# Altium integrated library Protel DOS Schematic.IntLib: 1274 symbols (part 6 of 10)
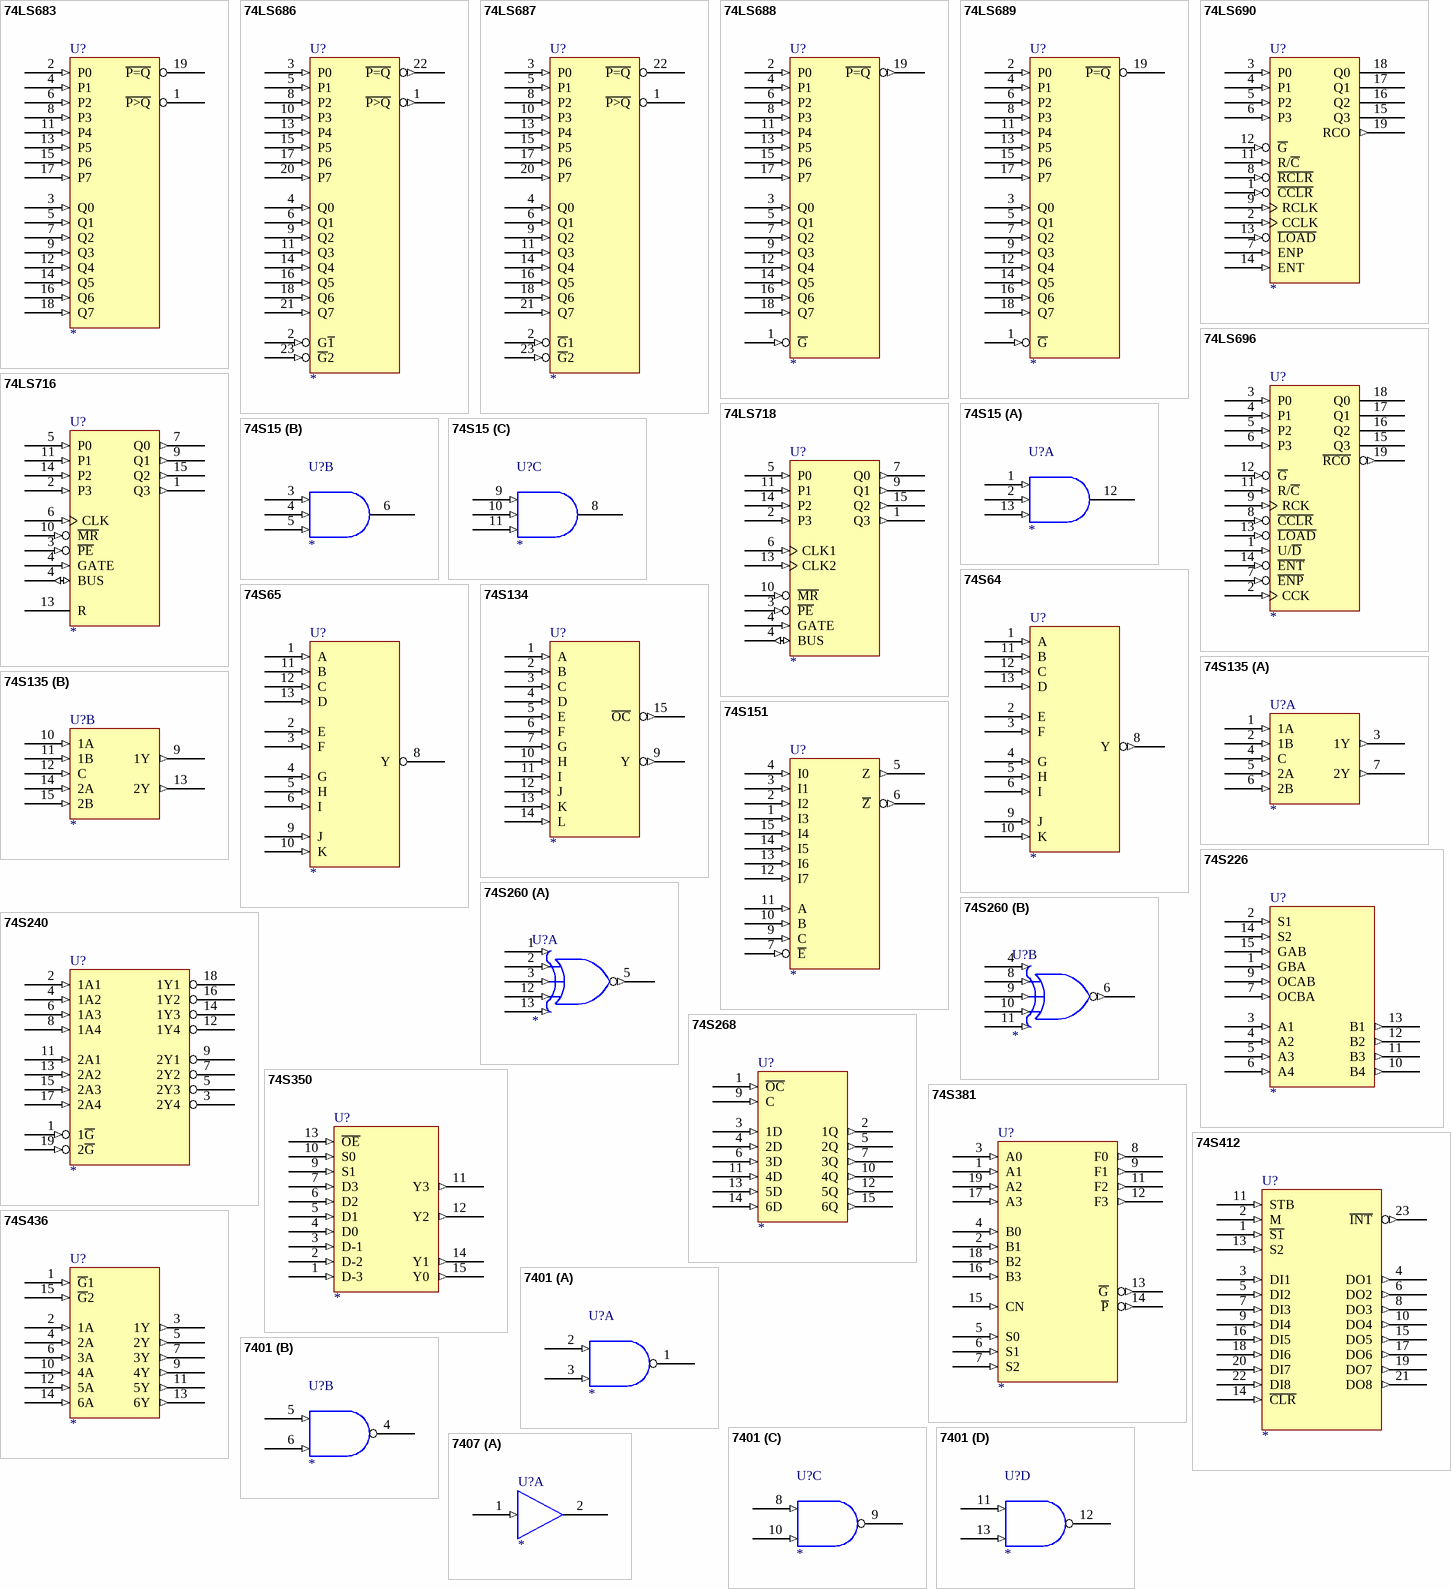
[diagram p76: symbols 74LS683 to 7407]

## 74S412
designator U?
footprint DIP-24
pins: 1 ~{S1} (in), 2 M (in), 3 DI1 (in), 4 DO1 (out), 5 DI2 (in), 6 DO2 (out), 7 DI3 (in), 8 DO3 (out), 9 DI4 (in), 10 DO4 (out), 11 STB (in), 12 GND (power) hidden to GND, 13 S2 (in), 14 ~{CLR} (in), 15 DO5 (out), 16 DI5 (in), 17 DO6 (out), 18 DI6 (in), 19 DO7 (out), 20 DI7 (in), 21 DO8 (out), 22 DI8 (in), 23 ~{INT} (out), 24 VCC (power) hidden to VCC
2 alternate drawings of the same symbol

## 74S436
designator U?
footprint DIP-16
pins: 1 ~{G}1 (in), 2 1A (in), 3 1Y (out), 4 2A (in), 5 2Y (out), 6 3A (in), 7 3Y (out), 8 GND (power) hidden to GND, 9 4Y (out), 10 4A (in), 11 5Y (out), 12 5A (in), 13 6Y (out), 14 6A (in), 15 ~{G}2 (in), 16 VCC (power) hidden to VCC
2 alternate drawings of the same symbol

## 7401
designator U?
footprint DIP-14
part A pins: 1 (oc), 2 (in), 3 (in), 7 GND (power) hidden to GND, 14 VCC (power) hidden to VCC
part B pins: 4 (oc), 5 (in), 6 (in), 7 GND (power) hidden to GND, 14 VCC (power) hidden to VCC
part C pins: 7 GND (power) hidden to GND, 8 (in), 9 (oc), 10 (in), 14 VCC (power) hidden to VCC
part D pins: 7 GND (power) hidden to GND, 11 (in), 12 (oc), 13 (in), 14 VCC (power) hidden to VCC
2 alternate drawings of the same symbol

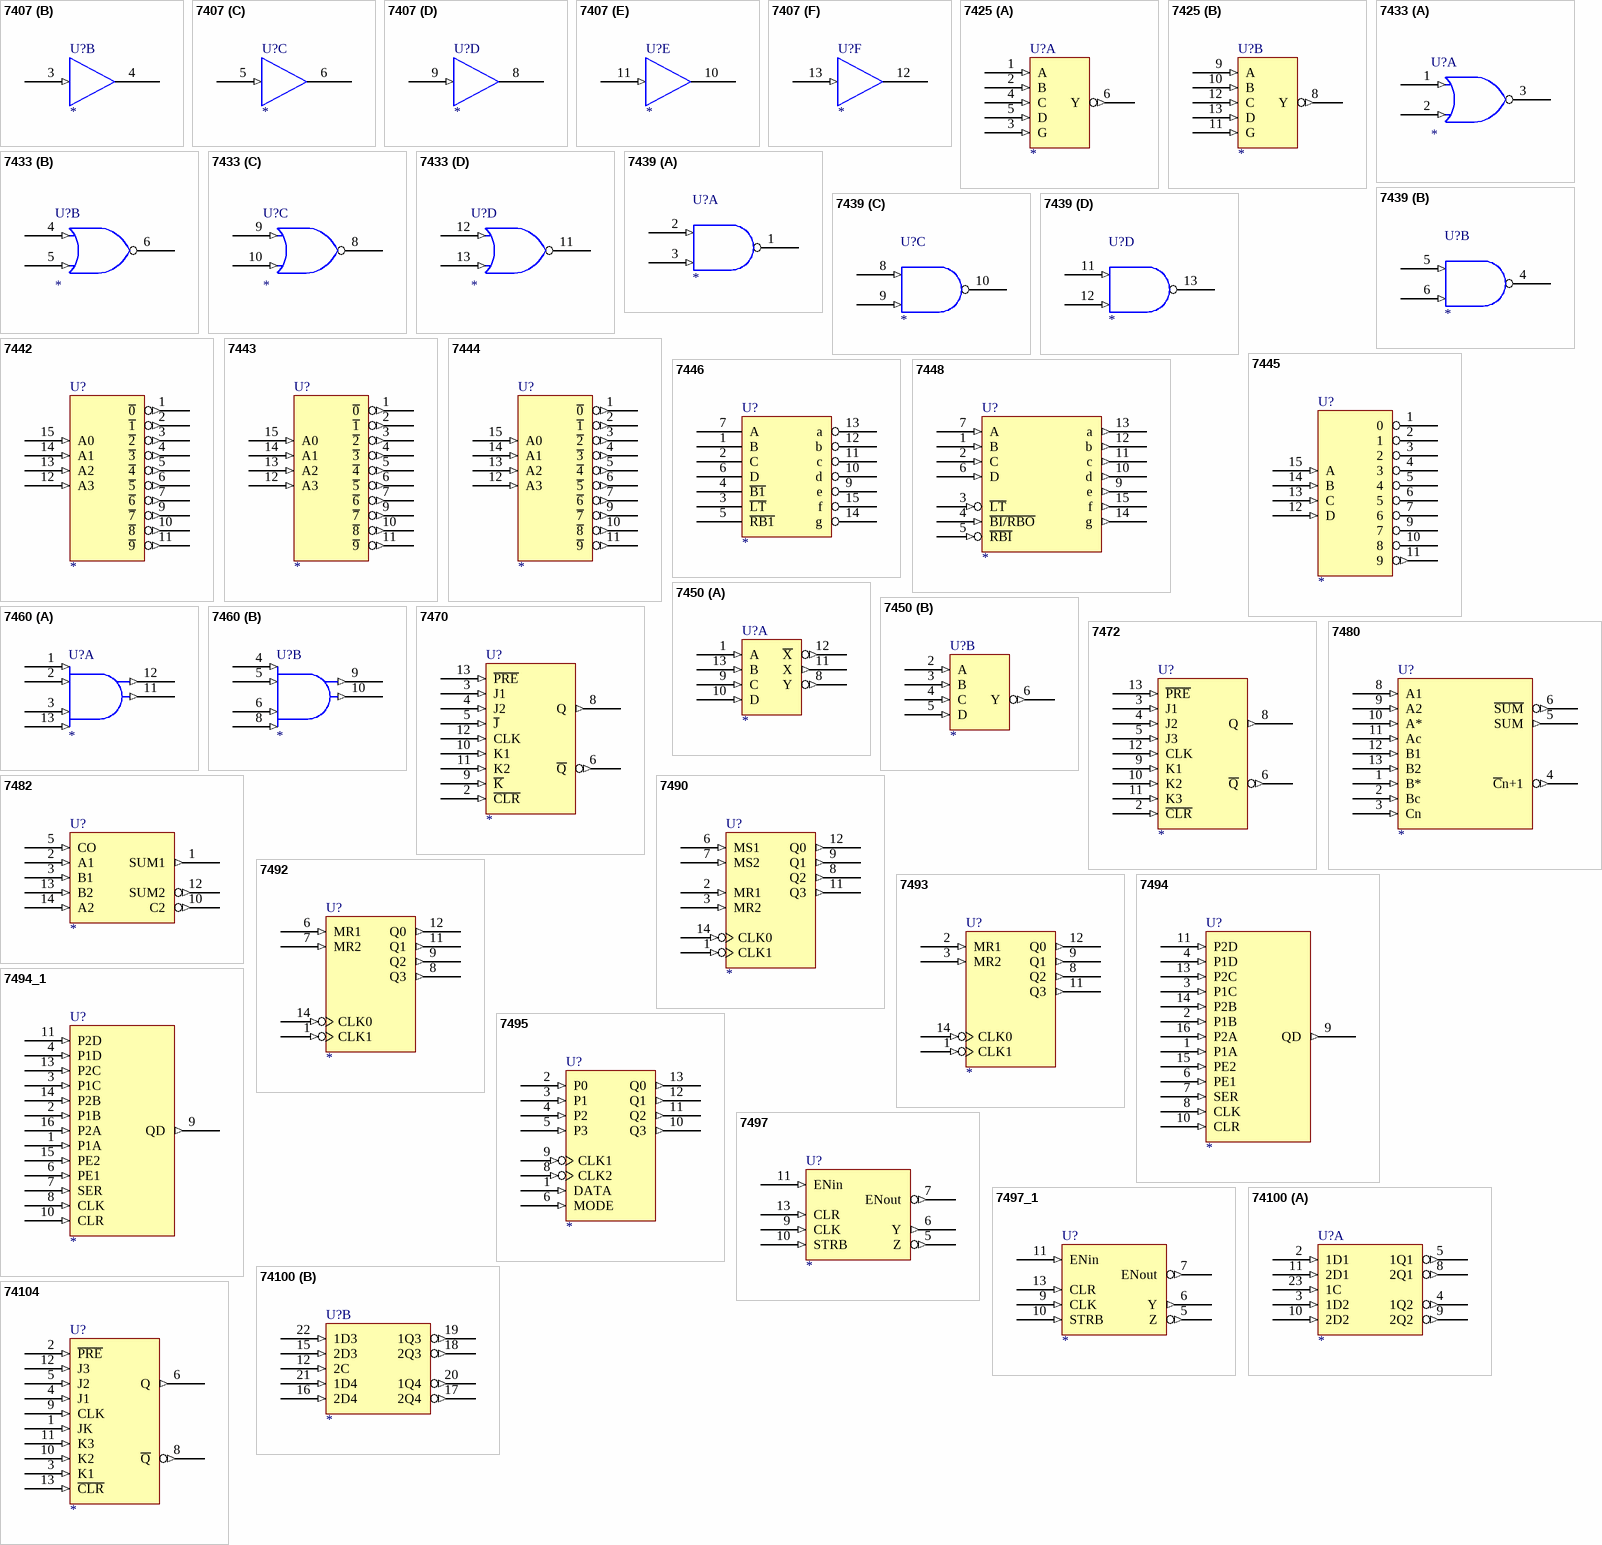
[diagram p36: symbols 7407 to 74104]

## 7407
designator U?
footprint DIP-14
part A pins: 1 (in), 2 (oc), 7 GND (power) hidden to GND, 14 VCC (power) hidden to VCC
part B pins: 3 (in), 4 (oc), 7 GND (power) hidden to GND, 14 VCC (power) hidden to VCC
part C pins: 5 (in), 6 (oc), 7 GND (power) hidden to GND, 14 VCC (power) hidden to VCC
part D pins: 7 GND (power) hidden to GND, 8 (oc), 9 (in), 14 VCC (power) hidden to VCC
part E pins: 7 GND (power) hidden to GND, 10 (oc), 11 (in), 14 VCC (power) hidden to VCC
part F pins: 7 GND (power) hidden to GND, 12 (oc), 13 (in), 14 VCC (power) hidden to VCC
2 alternate drawings of the same symbol

## 7425
designator U?
footprint DIP-14
part A pins: 1 A (in), 2 B (in), 3 G (in), 4 C (in), 5 D (in), 6 Y (out), 7 GND (power) hidden to GND, 14 VCC (power) hidden to VCC
part B pins: 7 GND (power) hidden to GND, 8 Y (out), 9 A (in), 10 B (in), 11 G (in), 12 C (in), 13 D (in), 14 VCC (power) hidden to VCC
2 alternate drawings of the same symbol

## 7433
designator U?
footprint DIP-14
part A pins: 1 (in), 2 (in), 3 (oc), 7 GND (power) hidden to GND, 14 VCC (power) hidden to VCC
part B pins: 4 (in), 5 (in), 6 (oc), 7 GND (power) hidden to GND, 14 VCC (power) hidden to VCC
part C pins: 7 GND (power) hidden to GND, 8 (oc), 9 (in), 10 (in), 14 VCC (power) hidden to VCC
part D pins: 7 GND (power) hidden to GND, 11 (oc), 12 (in), 13 (in), 14 VCC (power) hidden to VCC
2 alternate drawings of the same symbol

## 7439
designator U?
footprint DIP-14
part A pins: 1 (oc), 2 (in), 3 (in), 7 GND (power) hidden to GND, 14 VCC (power) hidden to VCC
part B pins: 4 (oc), 5 (in), 6 (in), 7 GND (power) hidden to GND, 14 VCC (power) hidden to VCC
part C pins: 7 GND (power) hidden to GND, 8 (in), 9 (in), 10 (oc), 14 VCC (power) hidden to VCC
part D pins: 7 GND (power) hidden to GND, 11 (in), 12 (in), 13 (oc), 14 VCC (power) hidden to VCC
2 alternate drawings of the same symbol

## 7442
designator U?
footprint DIP-16
pins: 1 ~{0} (out), 2 ~{1} (out), 3 ~{2} (out), 4 ~{3} (out), 5 ~{4} (out), 6 ~{5} (out), 7 ~{6} (out), 8 GND (power) hidden to GND, 9 ~{7} (out), 10 ~{8} (out), 11 ~{9} (out), 12 A3 (in), 13 A2 (in), 14 A1 (in), 15 A0 (in), 16 VCC (power) hidden to VCC
2 alternate drawings of the same symbol

## 7443
designator U?
footprint DIP-16
pins: 1 ~{0} (out), 2 ~{1} (out), 3 ~{2} (out), 4 ~{3} (out), 5 ~{4} (out), 6 ~{5} (out), 7 ~{6} (out), 8 GND (power) hidden to GND, 9 ~{7} (out), 10 ~{8} (out), 11 ~{9} (out), 12 A3 (in), 13 A2 (in), 14 A1 (in), 15 A0 (in), 16 VCC (power) hidden to VCC
2 alternate drawings of the same symbol

## 7444
designator U?
footprint DIP-16
pins: 1 ~{0} (out), 2 ~{1} (out), 3 ~{2} (out), 4 ~{3} (out), 5 ~{4} (out), 6 ~{5} (out), 7 ~{6} (out), 8 GND (power) hidden to GND, 9 ~{7} (out), 10 ~{8} (out), 11 ~{9} (out), 12 A3 (in), 13 A2 (in), 14 A1 (in), 15 A0 (in), 16 VCC (power) hidden to VCC
2 alternate drawings of the same symbol

## 7445
designator U?
footprint DIP-16
pins: 1 0 (oc), 2 1 (oc), 3 2 (oc), 4 3 (oc), 5 4 (oc), 6 5 (oc), 7 6 (oc), 8 GND (power) hidden to GND, 9 7 (oc), 10 8 (oc), 11 9 (out), 12 D (in), 13 C (in), 14 B (in), 15 A (in), 16 VCC (power) hidden to VCC
2 alternate drawings of the same symbol

## 7446
designator U?
footprint DIP16E
pins: 1 B, 2 C, 3 ~{LT}, 4 ~{B1}, 5 ~{RB1}, 6 D, 7 A, 8 GND (power) hidden to GND, 9 e (oc), 10 d (oc), 11 c (oc), 12 b (oc), 13 a (oc), 14 g (oc), 15 f (oc), 16 VCC (power) hidden to VCC
2 alternate drawings of the same symbol

## 7448
designator U?
footprint DIP-16
pins: 1 B (in), 2 C (in), 3 ~{LT} (in), 4 ~{BI/RBO} (in), 5 ~{RBI} (in), 6 D (in), 7 A (in), 8 GND (power) hidden to GND, 9 e (out), 10 d (out), 11 c (out), 12 b (out), 13 a (out), 14 g (out), 15 f (out), 16 VCC (power) hidden to VCC
2 alternate drawings of the same symbol

## 7450
designator U?
footprint DIP-14
part A pins: 1 A (in), 7 GND (power) hidden to GND, 8 Y (out), 9 C (in), 10 D (in), 11 X (out), 12 ~{X} (out), 13 B (in)
part B pins: 2 A (in), 3 B (in), 4 C (in), 5 D (in), 6 Y (out), 7 GND (power) hidden to GND
2 alternate drawings of the same symbol

## 7460
designator U?
footprint DIP-14
part A pins: 1 (in), 2 (in), 3 (in), 7 GND (power) hidden to GND, 11 (out), 12 (out), 13 (in), 14 VCC (power) hidden to VCC
part B pins: 4 (in), 5 (in), 6 (in), 7 GND (power) hidden to GND, 8 (in), 9 (out), 10 (out), 14 VCC (power) hidden to VCC
2 alternate drawings of the same symbol

## 7470
designator U?
footprint DIP-14
pins: 2 ~{CLR} (in), 3 J1 (in), 4 J2 (in), 5 ~{J} (in), 6 ~{Q} (out), 7 GND (power) hidden to GND, 8 Q (out), 9 ~{K} (in), 10 K1 (in), 11 K2 (in), 12 CLK (in), 13 ~{PRE} (in), 14 VCC (power) hidden to VCC
2 alternate drawings of the same symbol

## 7472
designator U?
footprint DIP-14
pins: 2 ~{CLR} (in), 3 J1 (in), 4 J2 (in), 5 J3 (in), 6 ~{Q} (out), 7 GND (power) hidden to GND, 8 Q (out), 9 K1 (in), 10 K2 (in), 11 K3 (in), 12 CLK (in), 13 ~{PRE} (in), 14 VCC (power) hidden to VCC
2 alternate drawings of the same symbol

## 7480
designator U?
footprint DIP-14
pins: 1 B* (in), 2 Bc (in), 3 Cn (in), 4 ~{C}n+1 (out), 5 SUM (out), 6 ~{SUM} (out), 7 GND (power) hidden to GND, 8 A1 (in), 9 A2 (in), 10 A* (in), 11 Ac (in), 12 B1 (in), 13 B2 (in), 14 VCC (power) hidden to VCC
2 alternate drawings of the same symbol

## 7482
designator U?
footprint DIP-14
pins: 1 SUM1 (out), 2 A1 (in), 3 B1 (in), 4 VCC (power) hidden to VCC, 5 CO (in), 10 C2 (out), 11 GND (power) hidden to GND, 12 SUM2 (out), 13 B2 (in), 14 A2 (in)
2 alternate drawings of the same symbol

## 7490
designator U?
footprint DIP-14
pins: 1 CLK1 (in), 2 MR1 (in), 3 MR2 (in), 5 VCC (power) hidden to VCC, 6 MS1 (in), 7 MS2 (in), 8 Q2 (out), 9 Q1 (out), 10 GND (power) hidden to GND, 11 Q3 (out), 12 Q0 (out), 14 CLK0 (in)
2 alternate drawings of the same symbol

## 7492
designator U?
footprint DIP-14
pins: 1 CLK1 (in), 5 VCC (power) hidden to VCC, 6 MR1 (in), 7 MR2 (in), 8 Q3 (out), 9 Q2 (out), 10 GND (power) hidden to GND, 11 Q1 (out), 12 Q0 (out), 14 CLK0 (in)
2 alternate drawings of the same symbol

## 7493
designator U?
footprint DIP-14
pins: 1 CLK1 (in), 2 MR1 (in), 3 MR2 (in), 5 VCC (power) hidden to VCC, 8 Q2 (out), 9 Q1 (out), 10 GND (power) hidden to GND, 11 Q3 (out), 12 Q0 (out), 14 CLK0 (in)
2 alternate drawings of the same symbol

## 7494
designator U?
footprint DIP-16
pins: 1 P1A (in), 2 P1B (in), 3 P1C (in), 4 P1D (in), 5 VCC (power) hidden to VCC, 6 PE1 (in), 7 SER (in), 8 CLK (in), 9 QD (out), 10 CLR (in), 11 P2D (in), 12 GND (power) hidden to GND, 13 P2C (in), 14 P2B (in), 15 PE2 (in), 16 P2A (in)
2 alternate drawings of the same symbol

## 7494_1
designator U?
footprint DIP-16
pins: 1 P1A (in), 2 P1B (in), 3 P1C (in), 4 P1D (in), 5 VCC (power) hidden to VCC, 6 PE1 (in), 7 SER (in), 8 CLK (in), 9 QD (out), 10 CLR (in), 11 P2D (in), 12 GND (power) hidden to GND, 13 P2C (in), 14 P2B (in), 15 PE2 (in), 16 P2A (in)
2 alternate drawings of the same symbol

## 7495
designator U?
footprint DIP-16
pins: 1 DATA (in), 2 P0 (in), 3 P1 (in), 4 P2 (in), 5 P3 (in), 6 MODE (in), 7 GND (power) hidden to GND, 8 CLK2 (in), 9 CLK1 (in), 10 Q3 (out), 11 Q2 (out), 12 Q1 (out), 13 Q0 (out), 16 VCC (power) hidden to VCC
2 alternate drawings of the same symbol

## 7497
designator U?
footprint DIP-16
pins: 5 Z (out), 6 Y (out), 7 ENout (out), 8 GND (power) hidden to GND, 9 CLK (in), 10 STRB (in), 11 ENin (in), 13 CLR (in), 16 VCC (power) hidden to VCC
2 alternate drawings of the same symbol

## 7497_1
designator U?
footprint DIP-16
pins: 5 Z (out), 6 Y (out), 7 ENout (out), 8 GND (power) hidden to GND, 9 CLK (in), 10 STRB (in), 11 ENin (in), 13 CLR (in), 16 VCC (power) hidden to VCC
2 alternate drawings of the same symbol

## 74100
designator U?
footprint DIP-24
part A pins: 2 1D1 (in), 3 1D2 (in), 4 1Q2 (out), 5 1Q1 (out), 7 GND (power) hidden to GND, 8 2Q1 (out), 9 2Q2 (out), 10 2D2 (in), 11 2D1 (in), 23 1C (in)
part B pins: 7 GND (power) hidden to GND, 12 2C (in), 15 2D3 (in), 16 2D4 (in), 17 2Q4 (out), 18 2Q3 (out), 19 1Q3 (out), 20 1Q4 (out), 21 1D4 (in), 22 1D3 (in)
2 alternate drawings of the same symbol

## 74104
designator U?
footprint DIP-14
pins: 1 JK (in), 2 ~{PRE} (in), 3 K1 (in), 4 J1 (in), 5 J2 (in), 6 Q (out), 7 GND (power) hidden to GND, 8 ~{Q} (out), 9 CLK (in), 10 K2 (in), 11 K3 (in), 12 J3 (in), 13 ~{CLR} (in), 14 VCC (power) hidden to VCC
2 alternate drawings of the same symbol

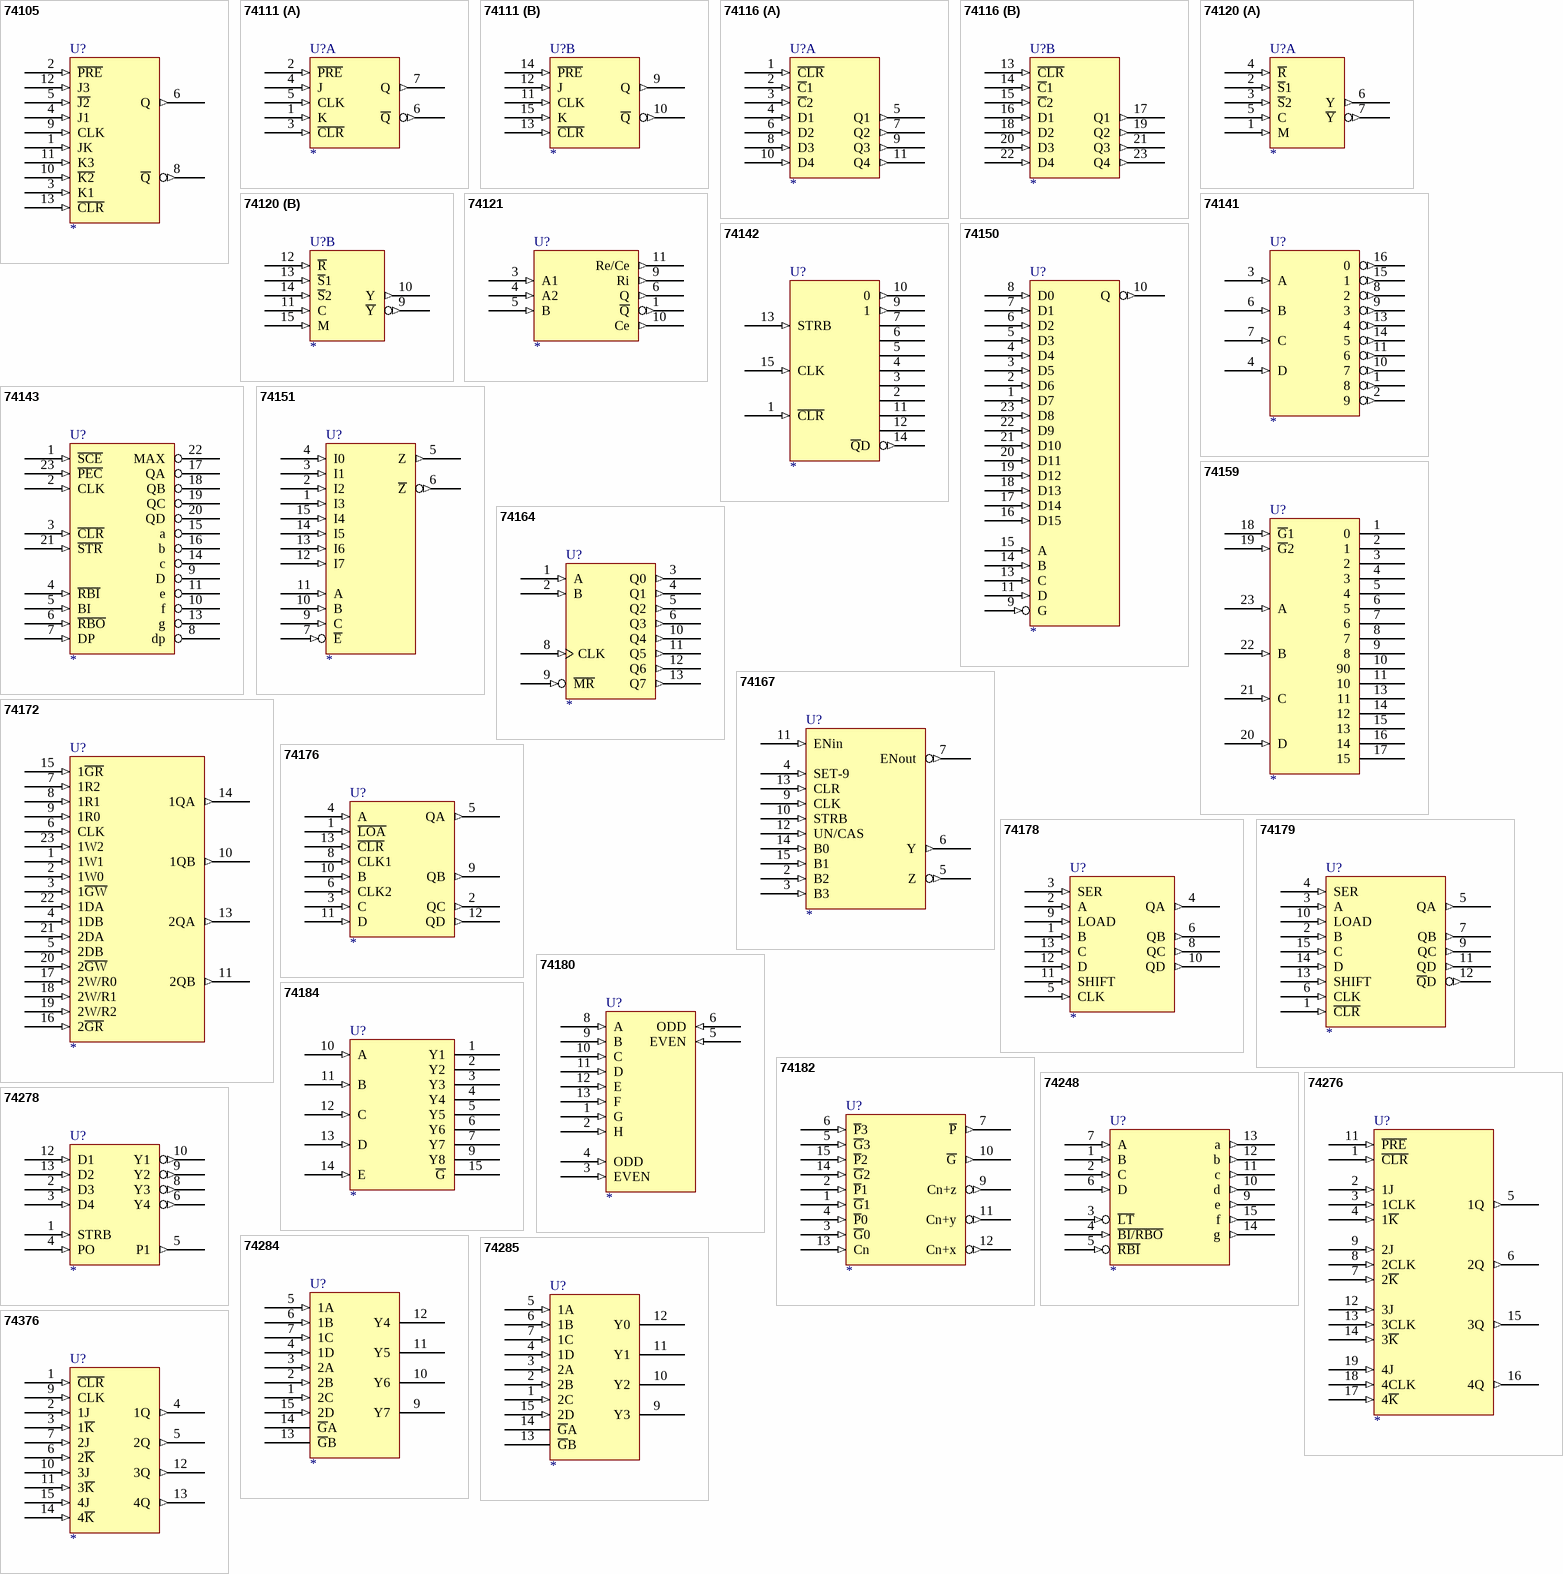
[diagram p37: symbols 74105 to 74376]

## 74105
designator U?
footprint DIP-14
pins: 1 JK (in), 2 ~{PRE} (in), 3 K1 (in), 4 J1 (in), 5 ~{J2} (in), 6 Q (out), 7 GND (power) hidden to GND, 8 ~{Q} (out), 9 CLK (in), 10 ~{K2} (in), 11 K3 (in), 12 J3 (in), 13 ~{CLR} (in), 14 VCC (power) hidden to VCC
2 alternate drawings of the same symbol

## 74111
designator U?
footprint DIP-16
part A pins: 1 K (in), 2 ~{PRE} (in), 3 ~{CLR} (in), 4 J (in), 5 CLK (in), 6 ~{Q} (out), 7 Q (out), 8 GND (power) hidden to GND, 16 VCC (power) hidden to VCC
part B pins: 8 GND (power) hidden to GND, 9 Q (out), 10 ~{Q} (out), 11 CLK (in), 12 J (in), 13 ~{CLR} (in), 14 ~{PRE} (in), 15 K (in), 16 VCC (power) hidden to VCC
2 alternate drawings of the same symbol

## 74116
designator U?
footprint DIP-24
part A pins: 1 ~{CLR} (in), 2 ~{C}1 (in), 3 ~{C}2 (in), 4 D1 (in), 5 Q1 (out), 6 D2 (in), 7 Q2 (out), 8 D3 (in), 9 Q3 (out), 10 D4 (in), 11 Q4 (out), 12 GND (power) hidden to GND, 24 VCC (power) hidden to VCC
part B pins: 12 GND (power) hidden to GND, 13 ~{CLR} (in), 14 ~{C}1 (in), 15 ~{C}2 (in), 16 D1 (in), 17 Q1 (out), 18 D2 (in), 19 Q2 (out), 20 D3 (in), 21 Q3 (out), 22 D4 (in), 23 Q4 (out), 24 VCC (power) hidden to VCC
2 alternate drawings of the same symbol

## 74120
designator U?
footprint DIP-16
part A pins: 1 M (in), 2 ~{S}1 (in), 3 ~{S}2 (in), 4 ~{R} (in), 5 C (in), 6 Y (out), 7 ~{Y} (out), 8 GND (power) hidden to GND, 16 VCC (power) hidden to VCC
part B pins: 8 GND (power) hidden to GND, 9 ~{Y} (out), 10 Y (out), 11 C (in), 12 ~{R} (in), 13 ~{S}1 (in), 14 ~{S}2 (in), 15 M (in), 16 VCC (power) hidden to VCC
2 alternate drawings of the same symbol

## 74121
designator U?
footprint DIP-14
pins: 1 ~{Q} (out), 3 A1 (in), 4 A2 (in), 5 B (in), 6 Q (out), 7 GND (power) hidden to GND, 9 Ri (out), 10 Ce (out), 11 Re/Ce (out), 14 VCC (power) hidden to VCC
2 alternate drawings of the same symbol

## 74141
designator U?
footprint DIP-16
pins: 1 8 (out), 2 9 (out), 3 A (in), 4 D (in), 5 VCC (power) hidden to VCC, 6 B (in), 7 C (in), 8 2 (out), 9 3 (out), 10 7 (out), 11 6 (out), 12 GND (power) hidden to GND, 13 4 (out), 14 5 (out), 15 1 (out), 16 0 (out)
2 alternate drawings of the same symbol

## 74142
designator U?
footprint DIP-16
pins: 1 ~{CLR} (in), 2, 3, 4, 5, 6, 7, 8 GND (power) hidden to GND, 9 1 (out), 10 0 (out), 11, 12, 13 STRB (in), 14 ~{Q}D (out), 15 CLK (in), 16 VCC (power) hidden to VCC
2 alternate drawings of the same symbol

## 74143
designator U?
footprint DIP-24
pins: 1 ~{SCE} (in), 2 CLK (in), 3 ~{CLR} (in), 4 ~{RBI} (in), 5 BI (in), 6 ~{RBO} (in), 7 DP (in), 8 dp (oc), 9 D (oc), 10 f (oc), 11 e (oc), 12 GND (power) hidden to GND, 13 g (oc), 14 c (oc), 15 a (oc), 16 b (oc), 17 QA (oc), 18 QB (oc), 19 QC (oc), 20 QD (oc), 21 ~{STR} (in), 22 MAX (oc), 23 ~{PEC} (in), 24 VCC (power) hidden to VCC
2 alternate drawings of the same symbol

## 74150
designator U?
footprint DIP-24
pins: 1 D7 (in), 2 D6 (in), 3 D5 (in), 4 D4 (in), 5 D3 (in), 6 D2 (in), 7 D1 (in), 8 D0 (in), 9 G (in), 10 Q (out), 11 D (in), 12 GND (power) hidden to GND, 13 C (in), 14 B (in), 15 A (in), 16 D15 (in), 17 D14 (in), 18 D13 (in), 19 D12 (in), 20 D11 (in), 21 D10 (in), 22 D9 (in), 23 D8 (in), 24 VCC (power) hidden to VCC
2 alternate drawings of the same symbol

## 74151
designator U?
footprint DIP-16
pins: 1 I3 (in), 2 I2 (in), 3 I1 (in), 4 I0 (in), 5 Z (out), 6 ~{Z} (out), 7 ~{E} (in), 8 GND (power) hidden to GND, 9 C (in), 10 B (in), 11 A (in), 12 I7 (in), 13 I6 (in), 14 I5 (in), 15 I4 (in), 16 VCC (power) hidden to VCC
2 alternate drawings of the same symbol

## 74159
designator U?
footprint DIP-24
pins: 1 0 (oc), 2 1 (oc), 3 2 (oc), 4 3 (oc), 5 4 (oc), 6 5 (oc), 7 6 (oc), 8 7 (oc), 9 8 (oc), 10 90 (oc), 11 10 (oc), 12 GND (power) hidden to GND, 13 11 (oc), 14 12 (oc), 15 13 (oc), 16 14 (oc), 17 15 (oc), 18 ~{G}1 (in), 19 ~{G}2 (in), 20 D (in), 21 C (in), 22 B (in), 23 A (in), 24 VCC (power) hidden to VCC
2 alternate drawings of the same symbol

## 74164
designator U?
footprint DIP-14
pins: 1 A (in), 2 B (in), 3 Q0 (out), 4 Q1 (out), 5 Q2 (out), 6 Q3 (out), 7 GND (power) hidden to GND, 8 CLK (in), 9 ~{MR} (in), 10 Q4 (out), 11 Q5 (out), 12 Q6 (out), 13 Q7 (out), 14 VCC (power) hidden to VCC
2 alternate drawings of the same symbol

## 74167
designator U?
footprint DIP-16
pins: 1 VCC (power) hidden to VCC, 2 B2 (in), 3 B3 (in), 4 SET-9 (in), 5 Z (out), 6 Y (out), 7 ENout (out), 8 GND (power) hidden to GND, 9 CLK (in), 10 STRB (in), 11 ENin (in), 12 UN/CAS (in), 13 CLR (in), 14 B0 (in), 15 B1 (in)
2 alternate drawings of the same symbol

## 74172
designator U?
footprint DIP-24
pins: 1 1W1 (in), 2 1W0 (in), 3 1~{GW} (in), 4 1DB (in), 5 2DB (in), 6 CLK (in), 7 1R2 (in), 8 1R1 (in), 9 1R0 (in), 10 1QB (out), 11 2QB (out), 12 GND (power) hidden to GND, 13 2QA (out), 14 1QA (out), 15 1~{GR} (in), 16 2~{GR} (in), 17 2W/R0 (in), 18 2W/R1 (in), 19 2W/R2 (in), 20 2~{GW} (in), 21 2DA (in), 22 1DA (in), 23 1W2 (in), 24 VCC (power) hidden to VCC
2 alternate drawings of the same symbol

## 74176
designator U?
footprint DIP-14
pins: 1 ~{LOA} (in), 2 QC (out), 3 C (in), 4 A (in), 5 QA (out), 6 CLK2 (in), 7 GND (power) hidden to GND, 8 CLK1 (in), 9 QB (out), 10 B (in), 11 D (in), 12 QD (out), 13 ~{CLR} (in), 14 VCC (power) hidden to VCC
2 alternate drawings of the same symbol

## 74178
designator U?
footprint DIP-14
pins: 1 B (in), 2 A (in), 3 SER (in), 4 QA (out), 5 CLK (in), 6 QB (out), 7 GND (power) hidden to GND, 8 QC (out), 9 LOAD (in), 10 QD (out), 11 SHIFT (in), 12 D (in), 13 C (in), 14 VCC (power) hidden to VCC
2 alternate drawings of the same symbol

## 74179
designator U?
footprint DIP-16
pins: 1 ~{CLR} (in), 2 B (in), 3 A (in), 4 SER (in), 5 QA (out), 6 CLK (in), 7 QB (out), 8 GND (power) hidden to GND, 9 QC (out), 10 LOAD (in), 11 QD (out), 12 ~{Q}D (out), 13 SHIFT (in), 14 D (in), 15 C (in), 16 VCC (power) hidden to VCC
2 alternate drawings of the same symbol

## 74180
designator U?
footprint DIP-14
pins: 1 G (in), 2 H (in), 3 EVEN (in), 4 ODD (in), 5 EVEN (in), 6 ODD (in), 7 GND (power) hidden to GND, 8 A (in), 9 B (in), 10 C (in), 11 D (in), 12 E (in), 13 F (in), 14 VCC (power) hidden to VCC
2 alternate drawings of the same symbol

## 74182
designator U?
footprint DIP-16
pins: 1 ~{G}1 (in), 2 ~{P}1 (in), 3 ~{G}0 (in), 4 ~{P}0 (in), 5 ~{G}3 (in), 6 ~{P}3 (in), 7 ~{P} (out), 8 GND (power) hidden to GND, 9 Cn+z (out), 10 ~{G} (out), 11 Cn+y (out), 12 Cn+x (out), 13 Cn (in), 14 ~{G}2 (in), 15 ~{P}2 (in), 16 VCC (power) hidden to VCC
2 alternate drawings of the same symbol

## 74184
designator U?
footprint DIP-16
pins: 1 Y1 (oc), 2 Y2 (oc), 3 Y3 (oc), 4 Y4 (oc), 5 Y5 (oc), 6 Y6 (oc), 7 Y7 (oc), 8 GND (power) hidden to GND, 9 Y8 (oc), 10 A (in), 11 B (in), 12 C (in), 13 D (in), 14 E (in), 15 ~{G} (oc), 16 VCC (power) hidden to VCC
2 alternate drawings of the same symbol

## 74248
designator U?
footprint DIP-16
pins: 1 B (in), 2 C (in), 3 ~{LT} (in), 4 ~{BI/RBO} (in), 5 ~{RBI} (in), 6 D (in), 7 A (in), 8 GND (power) hidden to GND, 9 e (out), 10 d (out), 11 c (out), 12 b (out), 13 a (out), 14 g (out), 15 f (out), 16 VCC (power) hidden to VCC
2 alternate drawings of the same symbol

## 74276
designator U?
footprint DIP-20
pins: 1 ~{CLR} (in), 2 1J (in), 3 1CLK (in), 4 1~{K} (in), 5 1Q (out), 6 2Q (out), 7 2~{K} (in), 8 2CLK (in), 9 2J (in), 10 GND (power) hidden to GND, 11 ~{PRE} (in), 12 3J (in), 13 3CLK (in), 14 3~{K} (in), 15 3Q (out), 16 4Q (out), 17 4~{K} (in), 18 4CLK (in), 19 4J (in), 20 VCC (power) hidden to VCC
2 alternate drawings of the same symbol

## 74278
designator U?
footprint DIP-14
pins: 1 STRB (in), 2 D3 (in), 3 D4 (in), 4 PO (in), 5 P1 (out), 6 Y4 (out), 7 GND (power) hidden to GND, 8 Y3 (out), 9 Y2 (out), 10 Y1 (out), 12 D1 (in), 13 D2 (in), 14 VCC (power) hidden to VCC
2 alternate drawings of the same symbol

## 74284
designator U?
footprint DIP-16
pins: 1 2C (in), 2 2B (in), 3 2A (in), 4 1D (in), 5 1A (in), 6 1B (in), 7 1C (in), 8 GND (power) hidden to GND, 9 Y7 (oc), 10 Y6 (oc), 11 Y5 (oc), 12 Y4 (oc), 13 ~{G}B, 14 ~{G}A, 15 2D (in), 16 VCC (power) hidden to VCC
2 alternate drawings of the same symbol

## 74285
designator U?
footprint DIP-16
pins: 1 2C (in), 2 2B (in), 3 2A (in), 4 1D (in), 5 1A (in), 6 1B (in), 7 1C (in), 8 GND (power) hidden to GND, 9 Y3 (oc), 10 Y2 (oc), 11 Y1 (oc), 12 Y0 (oc), 13 ~{G}B, 14 ~{G}A, 15 2D (in), 16 VCC (power) hidden to VCC
2 alternate drawings of the same symbol

## 74376
designator U?
footprint DIP-16
pins: 1 ~{CLR} (in), 2 1J (in), 3 1~{K} (in), 4 1Q (out), 5 2Q (out), 6 2~{K} (in), 7 2J (in), 8 GND (power) hidden to GND, 9 CLK (in), 10 3J (in), 11 3~{K} (in), 12 3Q (out), 13 4Q (out), 14 4~{K} (in), 15 4J (in), 16 VCC (power) hidden to VCC
2 alternate drawings of the same symbol


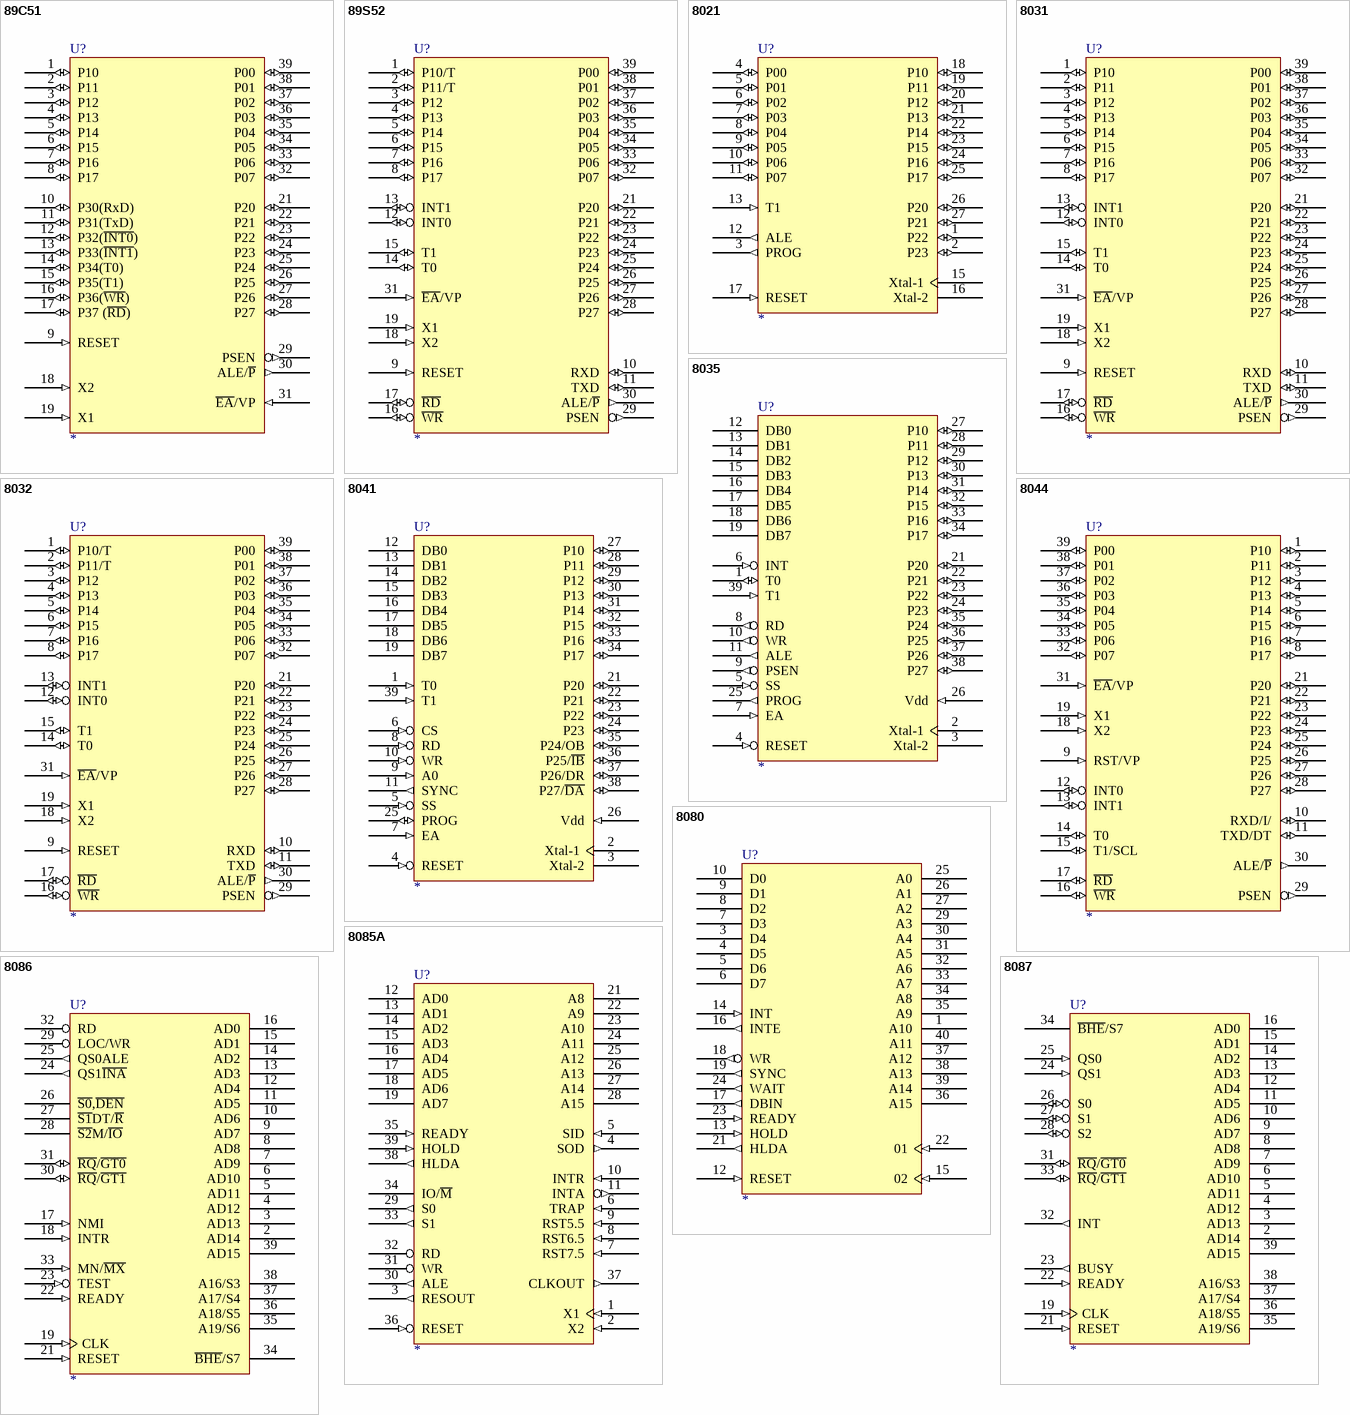
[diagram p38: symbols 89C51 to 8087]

## 89C51
designator U?
Microcontroller
footprint DIP40E
pins: 1 P10 (io), 2 P11 (io), 3 P12 (io), 4 P13 (io), 5 P14 (io), 6 P15 (io), 7 P16 (io), 8 P17 (io), 9 RESET (in), 10 P30(RxD) (io), 11 P31(TxD) (io), 12 P32(~{INT0}) (io), 13 P33(~{INT1}) (io), 14 P34(T0) (io), 15 P35(T1) (io), 16 P36(~{WR}) (io), 17 P37 (~{RD}) (io), 18 X2 (in), 19 X1 (in), 20 GND (power) hidden to GND, 21 P20 (io), 22 P21 (io), 23 P22 (io), 24 P23 (io), 25 P24 (io), 26 P25 (io), 27 P26 (io), 28 P27 (io), 29 PSEN (out), 30 ALE/~{P} (out), 31 ~{EA}/VP (in), 32 P07 (io), 33 P06 (io), 34 P05 (io), 35 P04 (io), 36 P03 (io), 37 P02 (io), 38 P01 (io), 39 P00 (io), 40 VCC (power) hidden to VCC
2 alternate drawings of the same symbol

## 89S52
designator U?
footprint DIP40E
pins: 1 P10/T (io), 2 P11/T (io), 3 P12 (io), 4 P13 (io), 5 P14 (io), 6 P15 (io), 7 P16 (io), 8 P17 (io), 9 RESET (in), 10 RXD (io), 11 TXD (io), 12 INT0 (io), 13 INT1 (io), 14 T0 (io), 15 T1 (io), 16 ~{WR} (io), 17 ~{RD} (io), 18 X2 (in), 19 X1 (in), 20 GND (power) hidden to GND, 21 P20 (io), 22 P21 (io), 23 P22 (io), 24 P23 (io), 25 P24 (io), 26 P25 (io), 27 P26 (io), 28 P27 (io), 29 PSEN (out), 30 ALE/~{P} (out), 31 ~{EA}/VP (in), 32 P07 (io), 33 P06 (io), 34 P05 (io), 35 P04 (io), 36 P03 (io), 37 P02 (io), 38 P01 (io), 39 P00 (io), 40 VCC (power) hidden to VCC
2 alternate drawings of the same symbol

## 8021
designator U?
footprint DIP-28
pins: 1 P22 (io), 2 P23 (io), 3 PROG (out), 4 P00 (io), 5 P01 (io), 6 P02 (io), 7 P03 (io), 8 P04 (io), 9 P05 (io), 10 P06 (io), 11 P07 (io), 12 ALE (out), 13 T1 (in), 14 GND (power) hidden to GND, 15 Xtal-1, 16 Xtal-2, 17 RESET (in), 18 P10 (io), 19 P11 (io), 20 P12 (io), 21 P13 (io), 22 P14 (io), 23 P15 (io), 24 P16 (io), 25 P17 (io), 26 P20 (io), 27 P21 (io), 28 VCC (power) hidden to VCC
2 alternate drawings of the same symbol

## 8031
designator U?
Microcontroller
footprint DIP40E
pins: 1 P10 (io), 2 P11 (io), 3 P12 (io), 4 P13 (io), 5 P14 (io), 6 P15 (io), 7 P16 (io), 8 P17 (io), 9 RESET (in), 10 RXD (io), 11 TXD (io), 12 INT0 (io), 13 INT1 (io), 14 T0 (io), 15 T1 (io), 16 ~{WR} (io), 17 ~{RD} (io), 18 X2 (in), 19 X1 (in), 20 GND (power) hidden to GND, 21 P20 (io), 22 P21 (io), 23 P22 (io), 24 P23 (io), 25 P24 (io), 26 P25 (io), 27 P26 (io), 28 P27 (io), 29 PSEN (out), 30 ALE/~{P} (out), 31 ~{EA}/VP (in), 32 P07 (io), 33 P06 (io), 34 P05 (io), 35 P04 (io), 36 P03 (io), 37 P02 (io), 38 P01 (io), 39 P00 (io), 40 VCC (power) hidden to VCC
2 alternate drawings of the same symbol

## 8032
designator U?
footprint DIP40E
pins: 1 P10/T (io), 2 P11/T (io), 3 P12 (io), 4 P13 (io), 5 P14 (io), 6 P15 (io), 7 P16 (io), 8 P17 (io), 9 RESET (in), 10 RXD (io), 11 TXD (io), 12 INT0 (io), 13 INT1 (io), 14 T0 (io), 15 T1 (io), 16 ~{WR} (io), 17 ~{RD} (io), 18 X2 (in), 19 X1 (in), 20 GND (power) hidden to GND, 21 P20 (io), 22 P21 (io), 23 P22 (io), 24 P23 (io), 25 P24 (io), 26 P25 (io), 27 P26 (io), 28 P27 (io), 29 PSEN (out), 30 ALE/~{P} (out), 31 ~{EA}/VP (in), 32 P07 (io), 33 P06 (io), 34 P05 (io), 35 P04 (io), 36 P03 (io), 37 P02 (io), 38 P01 (io), 39 P00 (io), 40 VCC (power) hidden to VCC
2 alternate drawings of the same symbol

## 8035
designator U?
footprint DIP-40
pins: 1 T0 (io), 2 Xtal-1, 3 Xtal-2, 4 RESET (in), 5 SS (in), 6 INT (in), 7 EA (in), 8 RD (out), 9 PSEN (out), 10 WR (out), 11 ALE (out), 12 DB0 (hiz), 13 DB1 (hiz), 14 DB2 (hiz), 15 DB3 (hiz), 16 DB4 (hiz), 17 DB5 (hiz), 18 DB6 (hiz), 19 DB7 (hiz), 20 GND (power) hidden to GND, 21 P20 (io), 22 P21 (io), 23 P22 (io), 24 P23 (io), 25 PROG (out), 26 Vdd (in), 27 P10 (io), 28 P11 (io), 29 P12 (io), 30 P13 (io), 31 P14 (io), 32 P15 (io), 33 P16 (io), 34 P17 (io), 35 P24 (io), 36 P25 (io), 37 P26 (io), 38 P27 (io), 39 T1 (in), 40 VCC (power) hidden to VCC
2 alternate drawings of the same symbol

## 8041
designator U?
footprint DIP-40
pins: 1 T0 (in), 2 Xtal-1, 3 Xtal-2, 4 RESET (in), 5 SS (in), 6 CS (in), 7 EA (in), 8 RD (in), 9 A0 (in), 10 WR (in), 11 SYNC (out), 12 DB0 (hiz), 13 DB1 (hiz), 14 DB2 (hiz), 15 DB3 (hiz), 16 DB4 (hiz), 17 DB5 (hiz), 18 DB6 (hiz), 19 DB7 (hiz), 20 GND (power) hidden to GND, 21 P20 (io), 22 P21 (io), 23 P22 (io), 24 P23 (io), 25 PROG (io), 26 Vdd (in), 27 P10 (io), 28 P11 (io), 29 P12 (io), 30 P13 (io), 31 P14 (io), 32 P15 (io), 33 P16 (io), 34 P17 (io), 35 P24/OB (io), 36 P25/~{IB} (io), 37 P26/DR (io), 38 P27/~{DA} (io), 39 T1 (in), 40 VCC (power) hidden to VCC
2 alternate drawings of the same symbol

## 8044
designator U?
footprint DIP-40
pins: 1 P10 (io), 2 P11 (io), 3 P12 (io), 4 P13 (io), 5 P14 (io), 6 P15 (io), 7 P16 (io), 8 P17 (io), 9 RST/VP (in), 10 RXD/I/ (io), 11 TXD/DT (io), 12 INT0 (io), 13 INT1 (io), 14 T0 (io), 15 T1/SCL (io), 16 ~{WR} (io), 17 ~{RD} (io), 18 X2 (in), 19 X1 (in), 20 GND (power) hidden to GND, 21 P20 (io), 22 P21 (io), 23 P22 (io), 24 P23 (io), 25 P24 (io), 26 P25 (io), 27 P26 (io), 28 P27 (io), 29 PSEN (out), 30 ALE/~{P} (out), 31 ~{EA}/VP (in), 32 P07 (io), 33 P06 (io), 34 P05 (io), 35 P04 (io), 36 P03 (io), 37 P02 (io), 38 P01 (io), 39 P00 (io), 40 VCC (power) hidden to VCC
2 alternate drawings of the same symbol

## 8080
designator U?
footprint DIP-40
pins: 1 A10 (hiz), 2 GND (power) hidden to GND, 3 D4 (hiz), 4 D5 (hiz), 5 D6 (hiz), 6 D7 (hiz), 7 D3 (hiz), 8 D2 (hiz), 9 D1 (hiz), 10 D0 (hiz), 11 -5 (power) hidden to -5, 12 RESET (in), 13 HOLD (in), 14 INT (in), 15 02 (in), 16 INTE (out), 17 DBIN (out), 18 WR (out), 19 SYNC (out), 20 VCC (power) hidden to VCC, 21 HLDA (out), 22 01 (in), 23 READY (in), 24 WAIT (out), 25 A0 (hiz), 26 A1 (hiz), 27 A2 (hiz), 28 +12 (power) hidden to +12, 29 A3 (hiz), 30 A4 (hiz), 31 A5 (hiz), 32 A6 (hiz), 33 A7 (hiz), 34 A8 (hiz), 35 A9 (hiz), 36 A15 (hiz), 37 A12 (hiz), 38 A13 (hiz), 39 A14 (hiz), 40 A11 (hiz)
2 alternate drawings of the same symbol

## 8085A
designator U?
footprint DIP-40
pins: 1 X1 (in), 2 X2 (in), 3 RESOUT (out), 4 SOD (out), 5 SID (in), 6 TRAP (in), 7 RST7.5 (in), 8 RST6.5 (in), 9 RST5.5 (in), 10 INTR (in), 11 INTA (out), 12 AD0 (hiz), 13 AD1 (hiz), 14 AD2 (hiz), 15 AD3 (hiz), 16 AD4 (hiz), 17 AD5 (hiz), 18 AD6 (hiz), 19 AD7 (hiz), 20 GND (power) hidden to GND, 21 A8 (hiz), 22 A9 (hiz), 23 A10 (hiz), 24 A11 (hiz), 25 A12 (hiz), 26 A13 (hiz), 27 A14 (hiz), 28 A15 (hiz), 29 S0 (out), 30 ALE (out), 31 WR (hiz), 32 RD (hiz), 33 S1 (out), 34 IO/~{M} (hiz), 35 READY (in), 36 RESET (in), 37 CLKOUT (out), 38 HLDA (out), 39 HOLD (in), 40 VCC (power) hidden to VCC
2 alternate drawings of the same symbol

## 8086
designator U?
footprint DIP-40
pins: 1 GND (power) hidden to GND, 2 AD14 (hiz), 3 AD13 (hiz), 4 AD12 (hiz), 5 AD11 (hiz), 6 AD10 (hiz), 7 AD9 (hiz), 8 AD8 (hiz), 9 AD7 (hiz), 10 AD6 (hiz), 11 AD5 (hiz), 12 AD4 (hiz), 13 AD3 (hiz), 14 AD2 (hiz), 15 AD1 (hiz), 16 AD0 (hiz), 17 NMI (in), 18 INTR (in), 19 CLK (in), 20 GND (power) hidden to GND, 21 RESET (in), 22 READY (in), 23 TEST (in), 24 QS1~{INA} (out), 25 QS0ALE (out), 26 ~{S0},~{DEN} (hiz), 27 ~{S1}DT/~{R} (hiz), 28 ~{S2}M/~{IO} (hiz), 29 LOC/WR (hiz), 30 ~{RQ}/~{GT1} (io), 31 ~{RQ}/~{GT0} (io), 32 RD (hiz), 33 MN/~{MX} (in), 34 ~{BHE}/S7 (hiz), 35 A19/S6 (hiz), 36 A18/S5 (hiz), 37 A17/S4 (hiz), 38 A16/S3 (hiz), 39 AD15 (hiz), 40 VCC (power) hidden to VCC
2 alternate drawings of the same symbol

## 8087
designator U?
footprint DIP-40
pins: 1 GND (power) hidden to GND, 2 AD14 (hiz), 3 AD13 (hiz), 4 AD12 (hiz), 5 AD11 (hiz), 6 AD10 (hiz), 7 AD9 (hiz), 8 AD8 (hiz), 9 AD7 (hiz), 10 AD6 (hiz), 11 AD5 (hiz), 12 AD4 (hiz), 13 AD3 (hiz), 14 AD2 (hiz), 15 AD1 (hiz), 16 AD0 (hiz), 19 CLK (in), 20 GND (power) hidden to GND, 21 RESET (in), 22 READY (in), 23 BUSY (out), 24 QS1 (in), 25 QS0 (in), 26 S0 (io), 27 S1 (io), 28 S2 (io), 31 ~{RQ}/~{GT0} (io), 32 INT (out), 33 ~{RQ}/~{GT1} (io), 34 ~{BHE}/S7 (hiz), 35 A19/S6 (hiz), 36 A18/S5 (hiz), 37 A17/S4 (hiz), 38 A16/S3 (hiz), 39 AD15 (hiz), 40 VCC (power) hidden to VCC
2 alternate drawings of the same symbol

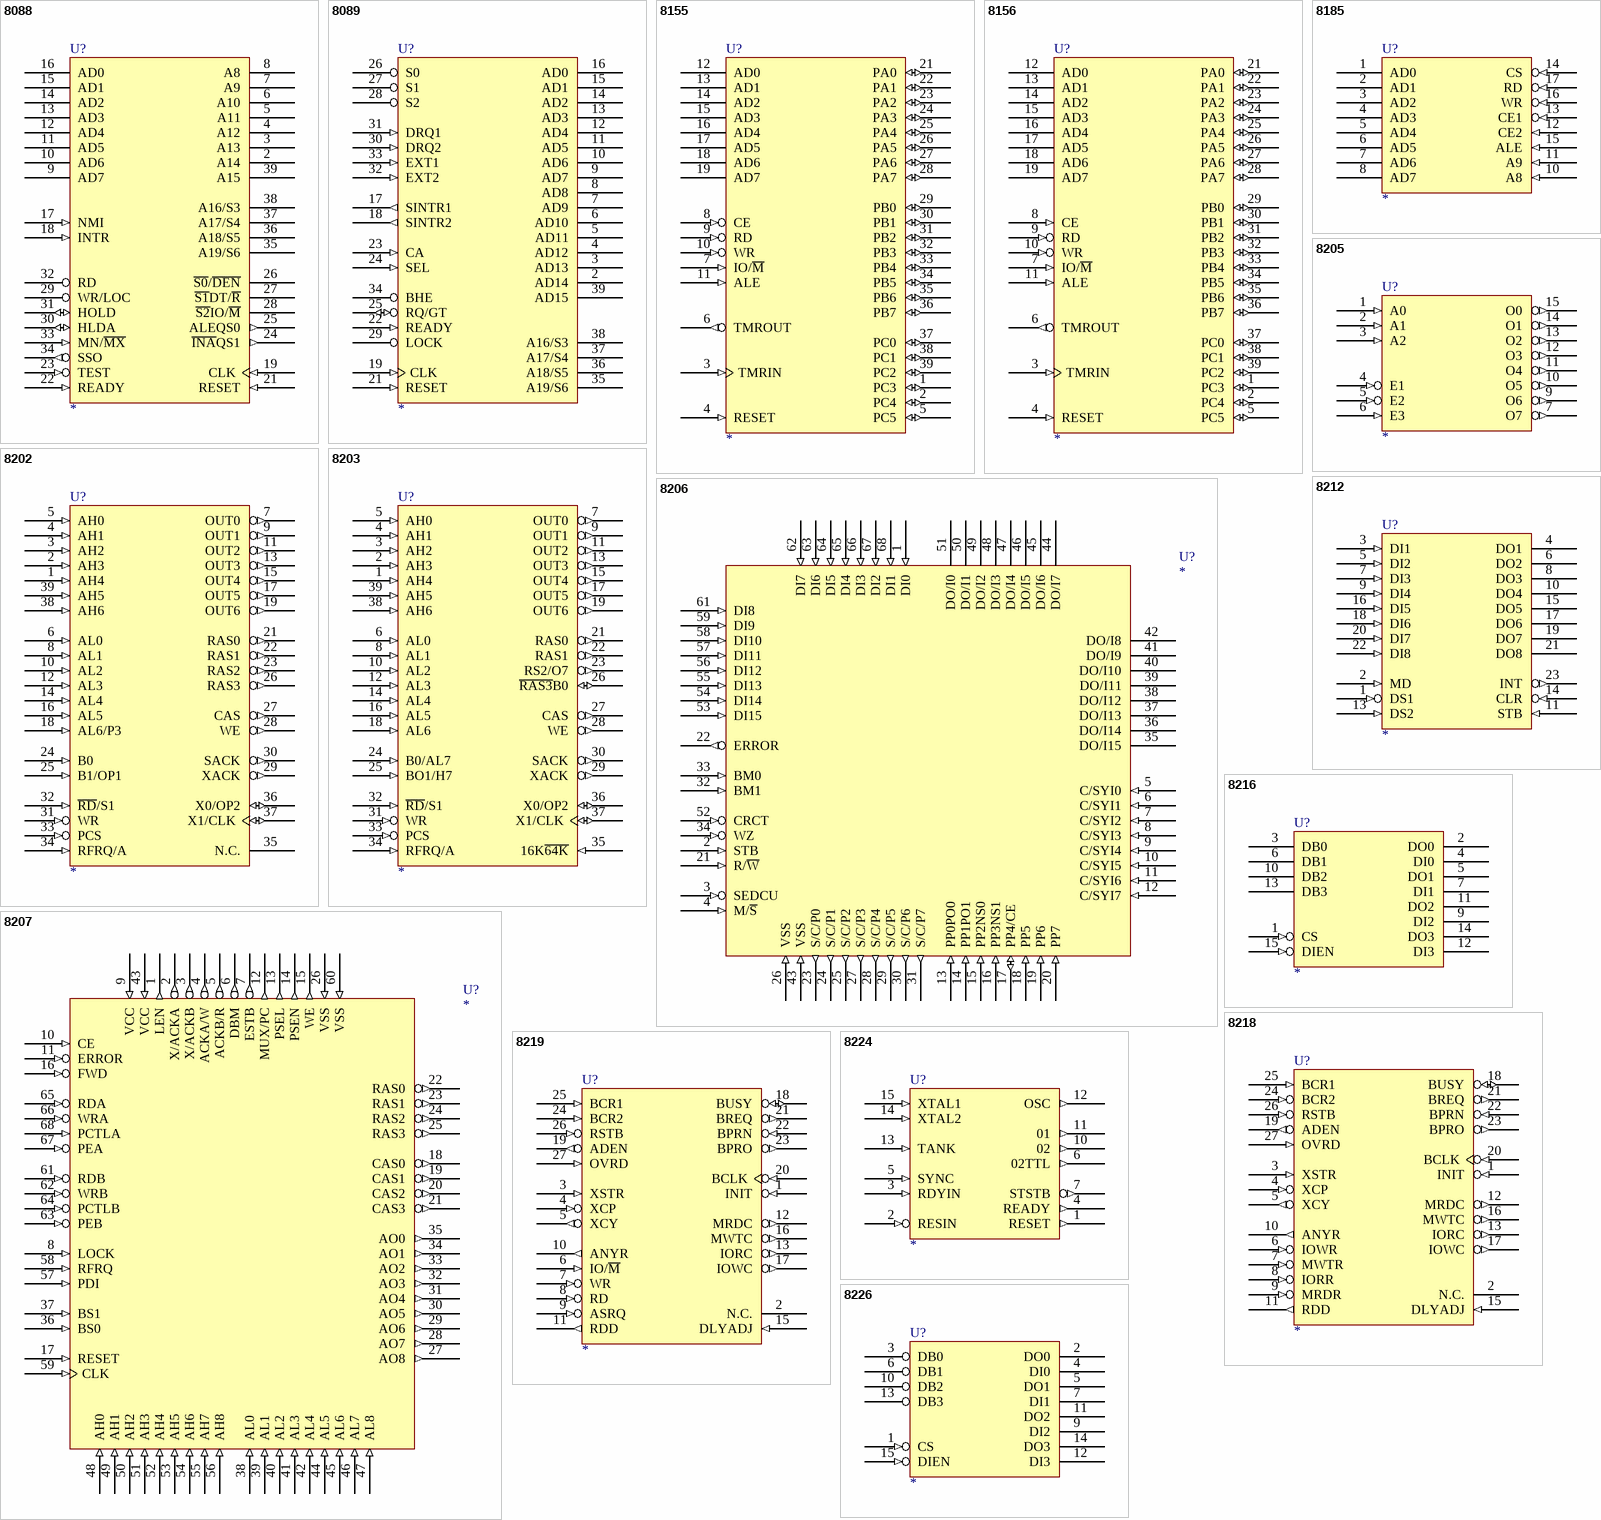
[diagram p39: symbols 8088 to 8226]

## 8088
designator U?
footprint DIP-40
pins: 1 GND (power) hidden to GND, 2 A14 (hiz), 3 A13 (hiz), 4 A12 (hiz), 5 A11 (hiz), 6 A10 (hiz), 7 A9 (hiz), 8 A8 (hiz), 9 AD7 (hiz), 10 AD6 (hiz), 11 AD5 (hiz), 12 AD4 (hiz), 13 AD3 (hiz), 14 AD2 (hiz), 15 AD1 (hiz), 16 AD0 (hiz), 17 NMI (in), 18 INTR (in), 19 CLK (in), 20 GND (power) hidden to GND, 21 RESET (in), 22 READY (in), 23 TEST (in), 24 ~{INA}QS1 (out), 25 ALEQS0 (out), 26 ~{S0}/~{DEN} (hiz), 27 ~{S1}DT/~{R} (hiz), 28 ~{S2}IO/~{M} (hiz), 29 WR/LOC (hiz), 30 HLDA (io), 31 HOLD (io), 32 RD (hiz), 33 MN/~{MX} (in), 34 SSO (out), 35 A19/S6 (hiz), 36 A18/S5 (hiz), 37 A17/S4 (hiz), 38 A16/S3 (hiz), 39 A15 (hiz), 40 VCC (power) hidden to VCC
2 alternate drawings of the same symbol

## 8089
designator U?
footprint DIP-40
pins: 1 GND (power) hidden to GND, 2 AD14 (hiz), 3 AD13 (hiz), 4 AD12 (hiz), 5 AD11 (hiz), 6 AD10 (hiz), 7 AD9 (hiz), 8 AD8 (hiz), 9 AD7 (hiz), 10 AD6 (hiz), 11 AD5 (hiz), 12 AD4 (hiz), 13 AD3 (hiz), 14 AD2 (hiz), 15 AD1 (hiz), 16 AD0 (hiz), 17 SINTR1 (out), 18 SINTR2 (out), 19 CLK (in), 20 GND (power) hidden to GND, 21 RESET (in), 22 READY (in), 23 CA (in), 24 SEL (in), 25 RQ/GT (io), 26 S0 (hiz), 27 S1 (hiz), 28 S2 (hiz), 29 LOCK (hiz), 30 DRQ2 (in), 31 DRQ1 (in), 32 EXT2 (in), 33 EXT1 (in), 34 BHE (hiz), 35 A19/S6 (hiz), 36 A18/S5 (hiz), 37 A17/S4 (hiz), 38 A16/S3 (hiz), 39 AD15 (hiz), 40 VCC (power) hidden to VCC
2 alternate drawings of the same symbol

## 8155
designator U?
footprint DIP-40
pins: 1 PC3 (io), 2 PC4 (io), 3 TMRIN (in), 4 RESET (in), 5 PC5 (io), 6 TMROUT (out), 7 IO/~{M} (in), 8 CE (in), 9 RD (in), 10 WR (in), 11 ALE (in), 12 AD0 (hiz), 13 AD1 (hiz), 14 AD2 (hiz), 15 AD3 (hiz), 16 AD4 (hiz), 17 AD5 (hiz), 18 AD6 (hiz), 19 AD7 (hiz), 20 GND (power) hidden to GND, 21 PA0 (io), 22 PA1 (io), 23 PA2 (io), 24 PA3 (io), 25 PA4 (io), 26 PA5 (io), 27 PA6 (io), 28 PA7 (io), 29 PB0 (io), 30 PB1 (io), 31 PB2 (io), 32 PB3 (io), 33 PB4 (io), 34 PB5 (io), 35 PB6 (io), 36 PB7 (io), 37 PC0 (io), 38 PC1 (io), 39 PC2 (io), 40 VCC (power) hidden to VCC
2 alternate drawings of the same symbol

## 8156
designator U?
footprint DIP-40
pins: 1 PC3 (io), 2 PC4 (io), 3 TMRIN (in), 4 RESET (in), 5 PC5 (io), 6 TMROUT (out), 7 IO/~{M} (in), 8 CE (in), 9 RD (in), 10 WR (in), 11 ALE (in), 12 AD0 (hiz), 13 AD1 (hiz), 14 AD2 (hiz), 15 AD3 (hiz), 16 AD4 (hiz), 17 AD5 (hiz), 18 AD6 (hiz), 19 AD7 (hiz), 20 GND (power) hidden to GND, 21 PA0 (io), 22 PA1 (io), 23 PA2 (io), 24 PA3 (io), 25 PA4 (io), 26 PA5 (io), 27 PA6 (io), 28 PA7 (io), 29 PB0 (io), 30 PB1 (io), 31 PB2 (io), 32 PB3 (io), 33 PB4 (io), 34 PB5 (io), 35 PB6 (io), 36 PB7 (io), 37 PC0 (io), 38 PC1 (io), 39 PC2 (io), 40 VCC (power) hidden to VCC
2 alternate drawings of the same symbol

## 8185
designator U?
footprint DIP-18
pins: 1 AD0 (hiz), 2 AD1 (hiz), 3 AD2 (hiz), 4 AD3 (hiz), 5 AD4 (hiz), 6 AD5 (hiz), 7 AD6 (hiz), 8 AD7 (hiz), 9 GND (power) hidden to GND, 10 A8 (in), 11 A9 (in), 12 CE2 (in), 13 CE1 (in), 14 CS (in), 15 ALE (in), 16 WR (in), 17 RD (in), 18 VCC (power) hidden to VCC
2 alternate drawings of the same symbol

## 8202
designator U?
footprint DIP-40
pins: 1 AH4 (in), 2 AH3 (in), 3 AH2 (in), 4 AH1 (in), 5 AH0 (in), 6 AL0 (in), 7 OUT0 (out), 8 AL1 (in), 9 OUT1 (out), 10 AL2 (in), 11 OUT2 (out), 12 AL3 (in), 13 OUT3 (out), 14 AL4 (in), 15 OUT4 (out), 16 AL5 (in), 17 OUT5 (out), 18 AL6/P3 (in), 19 OUT6 (out), 20 GND (power) hidden to GND, 21 RAS0 (out), 22 RAS1 (out), 23 RAS2 (out), 24 B0 (in), 25 B1/OP1 (in), 26 RAS3 (out), 27 CAS (out), 28 WE (out), 29 XACK (out), 30 SACK (out), 31 WR (in), 32 ~{RD}/S1 (in), 33 PCS (in), 34 RFRQ/A (in), 35 N.C., 36 X0/OP2 (io), 37 X1/CLK (io), 38 AH6 (in), 39 AH5 (in), 40 VCC (power) hidden to VCC
2 alternate drawings of the same symbol

## 8203
designator U?
footprint DIP-40
pins: 1 AH4 (in), 2 AH3 (in), 3 AH2 (in), 4 AH1 (in), 5 AH0 (in), 6 AL0 (in), 7 OUT0 (out), 8 AL1 (in), 9 OUT1 (out), 10 AL2 (in), 11 OUT2 (out), 12 AL3 (in), 13 OUT3 (out), 14 AL4 (in), 15 OUT4 (out), 16 AL5 (in), 17 OUT5 (out), 18 AL6 (in), 19 OUT6 (out), 20 GND (power) hidden to GND, 21 RAS0 (out), 22 RAS1 (out), 23 RS2/O7 (out), 24 B0/AL7 (in), 25 BO1/H7 (in), 26 ~{RAS3}B0 (io), 27 CAS (out), 28 WE (out), 29 XACK (out), 30 SACK (out), 31 WR (in), 32 ~{RD}/S1 (in), 33 PCS (in), 34 RFRQ/A (in), 35 16K~{64K} (in), 36 X0/OP2 (io), 37 X1/CLK (io), 38 AH6 (in), 39 AH5 (in), 40 VCC (power) hidden to VCC
2 alternate drawings of the same symbol

## 8205
designator U?
footprint DIP-16
pins: 1 A0 (in), 2 A1 (in), 3 A2 (in), 4 E1 (in), 5 E2 (in), 6 E3 (in), 7 O7 (out), 8 GND (power) hidden to GND, 9 O6 (out), 10 O5 (out), 11 O4 (out), 12 O3 (out), 13 O2 (out), 14 O1 (out), 15 O0 (out), 16 VCC (power) hidden to VCC
2 alternate drawings of the same symbol

## 8206
designator U?
footprint JEDECA-68
pins: 1 DI0 (in), 2 STB (in), 3 SEDCU (in), 4 M/~{S} (in), 5 C/SYI0 (in), 6 C/SYI1 (in), 7 C/SYI2 (in), 8 C/SYI3 (in), 9 C/SYI4 (in), 10 C/SYI5 (in), 11 C/SYI6 (in), 12 C/SYI7 (in), 13 PP0PO0 (in), 14 PP1PO1 (in), 15 PP2NS0 (in), 16 PP3NS1 (in), 17 PP4/CE (io), 18 PP5 (in), 19 PP6 (in), 20 PP7 (in), 21 R/~{W} (in), 22 ERROR (out), 23 S/C/P0 (out), 24 S/C/P1 (out), 25 S/C/P2 (out), 26 VSS (in), 27 S/C/P3 (out), 28 S/C/P4 (out), 29 S/C/P5 (out), 30 S/C/P6 (out), 31 S/C/P7 (out), 32 BM1 (in), 33 BM0 (in), 34 WZ (in), 35 DO/I15 (hiz), 36 DO/I14 (hiz), 37 DO/I13 (hiz), 38 DO/I12 (hiz), 39 DO/I11 (hiz), 40 DO/I10 (hiz), 41 DO/I9 (hiz), 42 DO/I8 (hiz), 43 VSS (in), 44 DO/I7 (hiz), 45 DO/I6 (hiz), 46 DO/I5 (hiz), 47 DO/I4 (hiz), 48 DO/I3 (hiz), 49 DO/I2 (hiz), 50 DO/I1 (hiz), 51 DO/I0 (hiz), 52 CRCT (in), 53 DI15 (in), 54 DI14 (in), 55 DI13 (in), 56 DI12 (in), 57 DI11 (in), 58 DI10 (in), 59 DI9 (in), 60 VCC (power) hidden to VCC, 61 DI8 (in), 62 DI7 (in), 63 DI6 (in), 64 DI5 (in), 65 DI4 (in), 66 DI3 (in), 67 DI2 (in), 68 DI1 (in)
2 alternate drawings of the same symbol

## 8207
designator U?
footprint JEDECA-68
pins: 1 LEN (out), 2 X/ACKA (out), 3 X/ACKB (out), 4 ACKA/W (out), 5 ACKB/R (out), 6 DBM (out), 7 ESTB (out), 8 LOCK (in), 9 VCC (in), 10 CE (in), 11 ERROR (in), 12 MUX/PC (out), 13 PSEL (out), 14 PSEN (out), 15 WE (out), 16 FWD (in), 17 RESET (in), 18 CAS0 (out), 19 CAS1 (out), 20 CAS2 (out), 21 CAS3 (out), 22 RAS0 (out), 23 RAS1 (out), 24 RAS2 (out), 25 RAS3 (out), 26 VSS (in), 27 AO8 (out), 28 AO7 (out), 29 AO6 (out), 30 AO5 (out), 31 AO4 (out), 32 AO3 (out), 33 AO2 (out), 34 AO1 (out), 35 AO0 (out), 36 BS0 (in), 37 BS1 (in), 38 AL0 (in), 39 AL1 (in), 40 AL2 (in), 41 AL3 (in), 42 AL4 (in), 43 VCC (in), 44 AL5 (in), 45 AL6 (in), 46 AL7 (in), 47 AL8 (in), 48 AH0 (in), 49 AH1 (in), 50 AH2 (in), 51 AH3 (in), 52 AH4 (in), 53 AH5 (in), 54 AH6 (in), 55 AH7 (in), 56 AH8 (in), 57 PDI (in), 58 RFRQ (in), 59 CLK (in), 60 VSS (in), 61 RDB (in), 62 WRB (in), 63 PEB (in), 64 PCTLB (in), 65 RDA (in), 66 WRA (in), 67 PEA (in), 68 PCTLA (in)
2 alternate drawings of the same symbol

## 8212
designator U?
footprint DIP-24
pins: 1 DS1 (in), 2 MD (in), 3 DI1 (in), 4 DO1 (hiz), 5 DI2 (in), 6 DO2 (hiz), 7 DI3 (in), 8 DO3 (hiz), 9 DI4 (in), 10 DO4 (hiz), 11 STB (in), 12 GND (power) hidden to GND, 13 DS2 (in), 14 CLR (in), 15 DO5 (hiz), 16 DI5 (in), 17 DO6 (hiz), 18 DI6 (in), 19 DO7 (hiz), 20 DI7 (in), 21 DO8 (hiz), 22 DI8 (in), 23 INT (out), 24 VCC (power) hidden to VCC
2 alternate drawings of the same symbol

## 8216
designator U?
footprint DIP-16
pins: 1 CS (in), 2 DO0 (hiz), 3 DB0 (hiz), 4 DI0 (hiz), 5 DO1 (hiz), 6 DB1 (hiz), 7 DI1 (hiz), 8 GND (power) hidden to GND, 9 DI2 (hiz), 10 DB2 (hiz), 11 DO2 (hiz), 12 DI3 (hiz), 13 DB3 (hiz), 14 DO3 (hiz), 15 DIEN (in), 16 VCC (power) hidden to VCC
2 alternate drawings of the same symbol

## 8218
designator U?
footprint DIP-28
pins: 1 INIT (in), 2 N.C., 3 XSTR (in), 4 XCP (in), 5 XCY (out), 6 IOWR (in), 7 MWTR (in), 8 IORR (in), 9 MRDR (in), 10 ANYR (out), 11 RDD (out), 12 MRDC (out), 13 IORC (out), 14 GND (power) hidden to GND, 15 DLYADJ (in), 16 MWTC (out), 17 IOWC (out), 18 BUSY (io), 19 ADEN (out), 20 BCLK (in), 21 BREQ (out), 22 BPRN (in), 23 BPRO (out), 24 BCR2 (in), 25 BCR1 (in), 26 RSTB (in), 27 OVRD (in), 28 VCC (power) hidden to VCC
2 alternate drawings of the same symbol

## 8219
designator U?
footprint DIP-28
pins: 1 INIT (in), 2 N.C., 3 XSTR (in), 4 XCP (in), 5 XCY (out), 6 IO/~{M} (in), 7 WR (in), 8 RD (in), 9 ASRQ (in), 10 ANYR (out), 11 RDD (out), 12 MRDC (out), 13 IORC (out), 14 GND (power) hidden to GND, 15 DLYADJ (in), 16 MWTC (out), 17 IOWC (out), 18 BUSY (io), 19 ADEN (out), 20 BCLK (in), 21 BREQ (out), 22 BPRN (in), 23 BPRO (out), 24 BCR2 (in), 25 BCR1 (in), 26 RSTB (in), 27 OVRD (in), 28 VCC (power) hidden to VCC
2 alternate drawings of the same symbol

## 8224
designator U?
footprint DIP-16
pins: 1 RESET (out), 2 RESIN (in), 3 RDYIN (in), 4 READY (out), 5 SYNC (in), 6 02TTL (out), 7 STSTB (out), 8 GND (power) hidden to GND, 9 VDD (power) hidden to VDD, 10 02 (out), 11 01 (out), 12 OSC (out), 13 TANK (in), 14 XTAL2 (in), 15 XTAL1 (in), 16 VCC (power) hidden to VCC
2 alternate drawings of the same symbol

## 8226
designator U?
footprint DIP-16
pins: 1 CS (in), 2 DO0 (hiz), 3 DB0 (hiz), 4 DI0 (hiz), 5 DO1 (hiz), 6 DB1 (hiz), 7 DI1 (hiz), 8 GND (power) hidden to GND, 9 DI2 (hiz), 10 DB2 (hiz), 11 DO2 (hiz), 12 DI3 (hiz), 13 DB3 (hiz), 14 DO3 (hiz), 15 DIEN (in), 16 VCC (power) hidden to VCC
2 alternate drawings of the same symbol

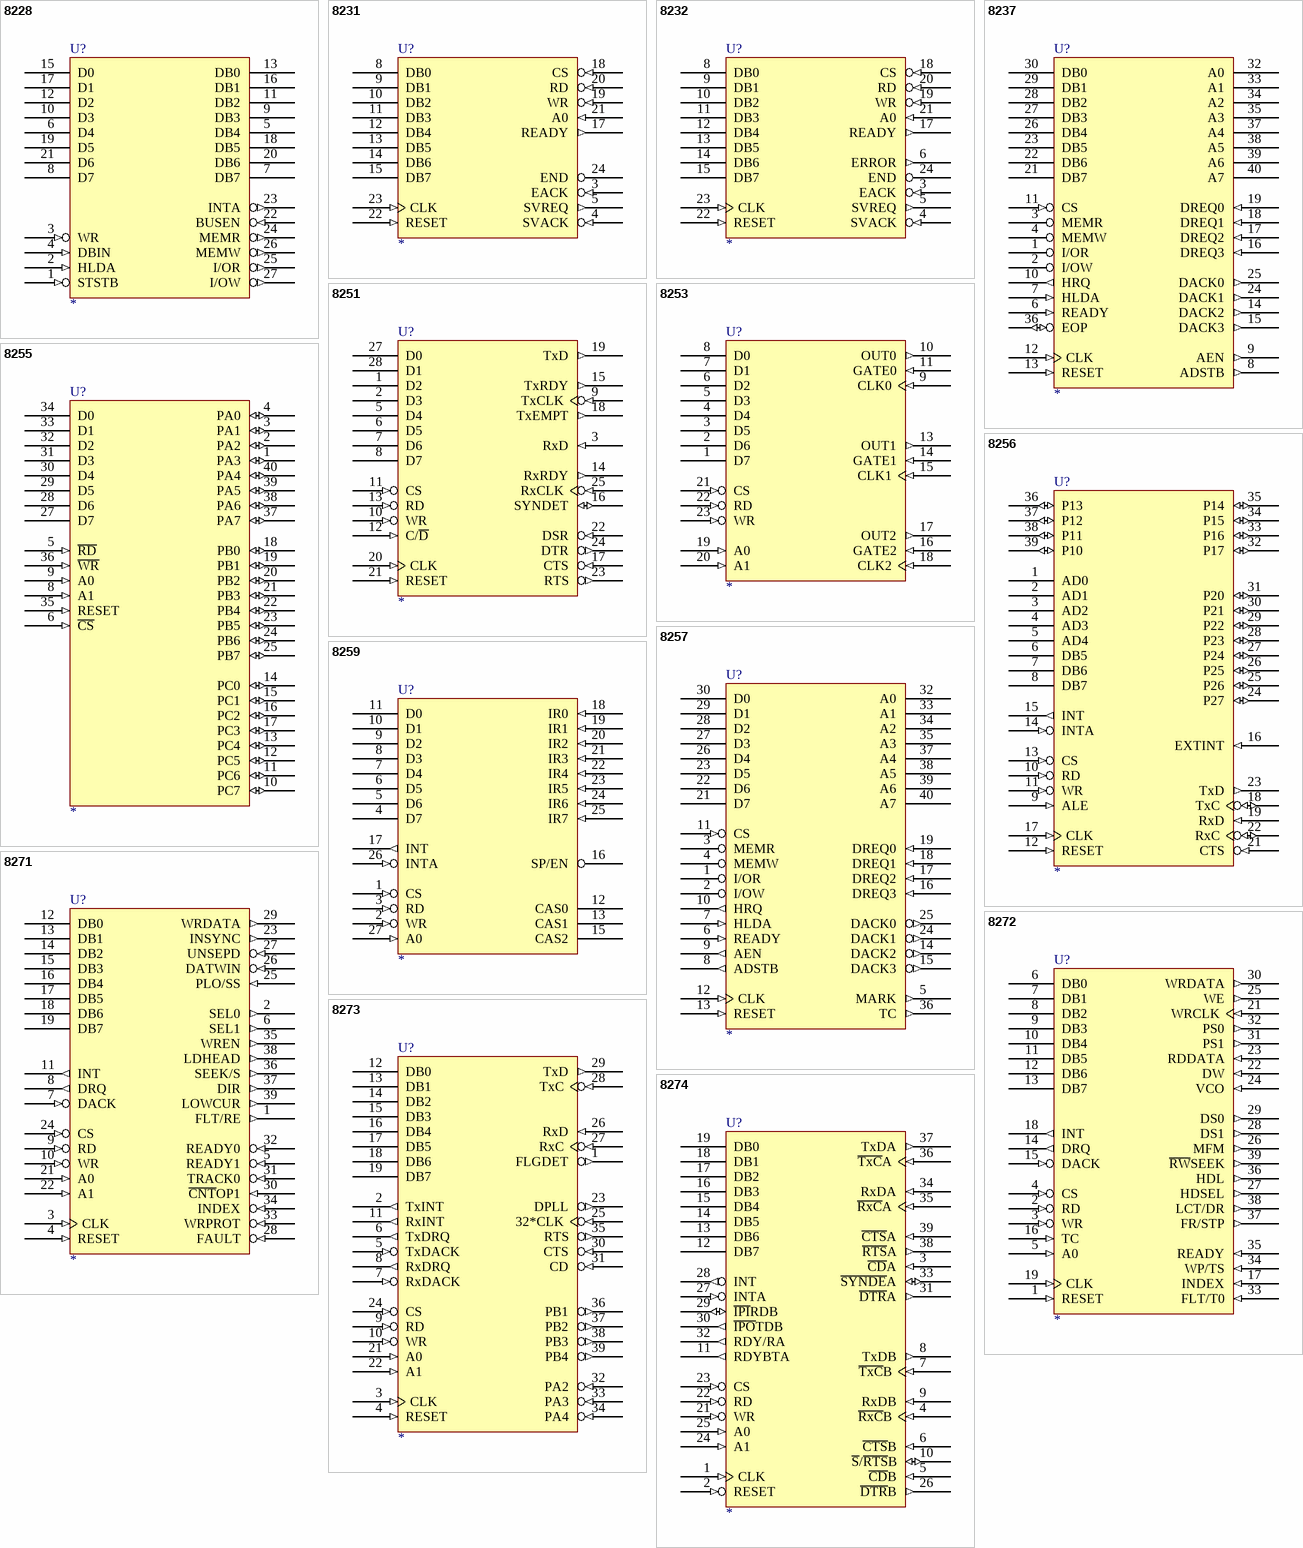
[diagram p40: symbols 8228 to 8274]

## 8228
designator U?
footprint DIP-28
pins: 1 STSTB (in), 2 HLDA (in), 3 WR (in), 4 DBIN (in), 5 DB4 (hiz), 6 D4 (hiz), 7 DB7 (hiz), 8 D7 (hiz), 9 DB3 (hiz), 10 D3 (hiz), 11 DB2 (hiz), 12 D2 (hiz), 13 DB0 (hiz), 14 GND (power) hidden to GND, 15 D0 (hiz), 16 DB1 (hiz), 17 D1 (hiz), 18 DB5 (hiz), 19 D5 (hiz), 20 DB6 (hiz), 21 D6 (hiz), 22 BUSEN (in), 23 INTA (out), 24 MEMR (out), 25 I/OR (out), 26 MEMW (out), 27 I/OW (out), 28 VCC (power) hidden to VCC
2 alternate drawings of the same symbol

## 8231
designator U?
footprint DIP-24
pins: 1 GND (power) hidden to GND, 2 VCC (power) hidden to VCC, 3 EACK (in), 4 SVACK (in), 5 SVREQ (out), 6 GND (power) hidden to GND, 7 GND (power) hidden to GND, 8 DB0 (hiz), 9 DB1 (hiz), 10 DB2 (hiz), 11 DB3 (hiz), 12 DB4 (hiz), 13 DB5 (hiz), 14 DB6 (hiz), 15 DB7 (hiz), 16 VDD (power) hidden to VDD, 17 READY (out), 18 CS (in), 19 WR (in), 20 RD (in), 21 A0 (in), 22 RESET (in), 23 CLK (in), 24 END (oc)
2 alternate drawings of the same symbol

## 8232
designator U?
footprint DIP-24
pins: 1 GND (power) hidden to GND, 2 VCC (power) hidden to VCC, 3 EACK (in), 4 SVACK (in), 5 SVREQ (out), 6 ERROR (out), 7 GND (power) hidden to GND, 8 DB0 (hiz), 9 DB1 (hiz), 10 DB2 (hiz), 11 DB3 (hiz), 12 DB4 (hiz), 13 DB5 (hiz), 14 DB6 (hiz), 15 DB7 (hiz), 16 VDD (power) hidden to VDD, 17 READY (out), 18 CS (in), 19 WR (in), 20 RD (in), 21 A0 (in), 22 RESET (in), 23 CLK (in), 24 END (oc)
2 alternate drawings of the same symbol

## 8237
designator U?
footprint DIP-40
pins: 1 I/OR (hiz), 2 I/OW (hiz), 3 MEMR (hiz), 4 MEMW (hiz), 5 VCC (power) hidden to VCC, 6 READY (in), 7 HLDA (in), 8 ADSTB (out), 9 AEN (out), 10 HRQ (out), 11 CS (in), 12 CLK (in), 13 RESET (in), 14 DACK2 (out), 15 DACK3 (out), 16 DREQ3 (in), 17 DREQ2 (in), 18 DREQ1 (in), 19 DREQ0 (in), 20 GND (power) hidden to GND, 21 DB7 (hiz), 22 DB6 (hiz), 23 DB5 (hiz), 24 DACK1 (out), 25 DACK0 (out), 26 DB4 (hiz), 27 DB3 (hiz), 28 DB2 (hiz), 29 DB1 (hiz), 30 DB0 (hiz), 31 VCC (power) hidden to VCC, 32 A0 (hiz), 33 A1 (hiz), 34 A2 (hiz), 35 A3 (hiz), 36 EOP (io), 37 A4 (hiz), 38 A5 (hiz), 39 A6 (hiz), 40 A7 (hiz)
2 alternate drawings of the same symbol

## 8251
designator U?
footprint DIP-28
pins: 1 D2 (hiz), 2 D3 (hiz), 3 RxD (in), 4 GND (power) hidden to GND, 5 D4 (hiz), 6 D5 (hiz), 7 D6 (hiz), 8 D7 (hiz), 9 TxCLK (in), 10 WR (in), 11 CS (in), 12 C/~{D} (in), 13 RD (in), 14 RxRDY (out), 15 TxRDY (out), 16 SYNDET (io), 17 CTS (in), 18 TxEMPT (out), 19 TxD (out), 20 CLK (in), 21 RESET (in), 22 DSR (in), 23 RTS (out), 24 DTR (out), 25 RxCLK (in), 26 VCC (power) hidden to VCC, 27 D0 (hiz), 28 D1 (hiz)
2 alternate drawings of the same symbol

## 8253
designator U?
footprint DIP-24
pins: 1 D7 (hiz), 2 D6 (hiz), 3 D5 (hiz), 4 D4 (hiz), 5 D3 (hiz), 6 D2 (hiz), 7 D1 (hiz), 8 D0 (hiz), 9 CLK0 (in), 10 OUT0 (out), 11 GATE0 (in), 12 GND (power) hidden to GND, 13 OUT1 (out), 14 GATE1 (in), 15 CLK1 (in), 16 GATE2 (in), 17 OUT2 (out), 18 CLK2 (in), 19 A0 (in), 20 A1 (in), 21 CS (in), 22 RD (in), 23 WR (in), 24 VCC (power) hidden to VCC
2 alternate drawings of the same symbol

## 8255
designator U?
footprint DIP-40
pins: 1 PA3 (io), 2 PA2 (io), 3 PA1 (io), 4 PA0 (io), 5 ~{RD} (in), 6 ~{CS} (in), 7 GND (power) hidden to GND, 8 A1 (in), 9 A0 (in), 10 PC7 (io), 11 PC6 (io), 12 PC5 (io), 13 PC4 (io), 14 PC0 (io), 15 PC1 (io), 16 PC2 (io), 17 PC3 (io), 18 PB0 (io), 19 PB1 (io), 20 PB2 (io), 21 PB3 (io), 22 PB4 (io), 23 PB5 (io), 24 PB6 (io), 25 PB7 (io), 26 VCC (power) hidden to VCC, 27 D7 (hiz), 28 D6 (hiz), 29 D5 (hiz), 30 D4 (hiz), 31 D3 (hiz), 32 D2 (hiz), 33 D1 (hiz), 34 D0 (hiz), 35 RESET (in), 36 ~{WR} (in), 37 PA7 (io), 38 PA6 (io), 39 PA5 (io), 40 PA4 (io)
2 alternate drawings of the same symbol

## 8256
designator U?
footprint DIP-40
pins: 1 AD0 (hiz), 2 AD1 (hiz), 3 AD2 (hiz), 4 AD3 (hiz), 5 AD4 (hiz), 6 DB5 (hiz), 7 DB6 (hiz), 8 DB7 (hiz), 9 ALE (in), 10 RD (in), 11 WR (in), 12 RESET (in), 13 CS (in), 14 INTA (in), 15 INT (out), 16 EXTINT (in), 17 CLK (in), 18 TxC (io), 19 RxD (in), 20 GND (power) hidden to GND, 21 CTS (in), 22 RxC (io), 23 TxD (out), 24 P27 (io), 25 P26 (io), 26 P25 (io), 27 P24 (io), 28 P23 (io), 29 P22 (io), 30 P21 (io), 31 P20 (io), 32 P17 (io), 33 P16 (io), 34 P15 (io), 35 P14 (io), 36 P13 (io), 37 P12 (io), 38 P11 (io), 39 P10 (io), 40 VCC (power) hidden to VCC
2 alternate drawings of the same symbol

## 8257
designator U?
footprint DIP-40
pins: 1 I/OR (hiz), 2 I/OW (hiz), 3 MEMR (hiz), 4 MEMW (hiz), 5 MARK (out), 6 READY (in), 7 HLDA (in), 8 ADSTB (out), 9 AEN (out), 10 HRQ (out), 11 CS (in), 12 CLK (in), 13 RESET (in), 14 DACK2 (out), 15 DACK3 (out), 16 DREQ3 (in), 17 DREQ2 (in), 18 DREQ1 (in), 19 DREQ0 (in), 20 GND (power) hidden to GND, 21 D7 (hiz), 22 D6 (hiz), 23 D5 (hiz), 24 DACK1 (out), 25 DACK0 (out), 26 D4 (hiz), 27 D3 (hiz), 28 D2 (hiz), 29 D1 (hiz), 30 D0 (hiz), 31 VCC (power) hidden to VCC, 32 A0 (hiz), 33 A1 (hiz), 34 A2 (hiz), 35 A3 (hiz), 36 TC (out), 37 A4 (hiz), 38 A5 (hiz), 39 A6 (hiz), 40 A7 (hiz)
2 alternate drawings of the same symbol

## 8259
designator U?
footprint DIP-28
pins: 1 CS (in), 2 WR (in), 3 RD (in), 4 D7 (hiz), 5 D6 (hiz), 6 D5 (hiz), 7 D4 (hiz), 8 D3 (hiz), 9 D2 (hiz), 10 D1 (hiz), 11 D0 (hiz), 12 CAS0 (hiz), 13 CAS1 (hiz), 14 GND (power) hidden to GND, 15 CAS2 (hiz), 16 SP/EN (hiz), 17 INT (out), 18 IR0 (in), 19 IR1 (in), 20 IR2 (in), 21 IR3 (in), 22 IR4 (in), 23 IR5 (in), 24 IR6 (in), 25 IR7 (in), 26 INTA (in), 27 A0 (in), 28 VCC (power) hidden to VCC
2 alternate drawings of the same symbol

## 8271
designator U?
footprint DIP-40
pins: 1 FLT/RE (out), 2 SEL0 (out), 3 CLK (in), 4 RESET (in), 5 READY1 (in), 6 SEL1 (out), 7 DACK (in), 8 DRQ (out), 9 RD (in), 10 WR (in), 11 INT (out), 12 DB0 (hiz), 13 DB1 (hiz), 14 DB2 (hiz), 15 DB3 (hiz), 16 DB4 (hiz), 17 DB5 (hiz), 18 DB6 (hiz), 19 DB7 (hiz), 20 GND (power) hidden to GND, 21 A0 (in), 22 A1 (in), 23 INSYNC (out), 24 CS (in), 25 PLO/SS (in), 26 DATWIN (in), 27 UNSEPD (in), 28 FAULT (in), 29 WRDATA (out), 30 ~{CNT}OP1 (in), 31 TRACK0 (in), 32 READY0 (in), 33 WRPROT (in), 34 INDEX (in), 35 WREN (out), 36 SEEK/S (out), 37 DIR (out), 38 LDHEAD (out), 39 LOWCUR (out), 40 VCC (power) hidden to VCC
2 alternate drawings of the same symbol

## 8272
designator U?
footprint DIP-40
pins: 1 RESET (in), 2 RD (in), 3 WR (in), 4 CS (in), 5 A0 (in), 6 DB0 (hiz), 7 DB1 (hiz), 8 DB2 (hiz), 9 DB3 (hiz), 10 DB4 (hiz), 11 DB5 (hiz), 12 DB6 (hiz), 13 DB7 (hiz), 14 DRQ (out), 15 DACK (in), 16 TC (in), 17 INDEX (in), 18 INT (out), 19 CLK (in), 20 GND (power) hidden to GND, 21 WRCLK (in), 22 DW (in), 23 RDDATA (in), 24 VCO (in), 25 WE (out), 26 MFM (out), 27 HDSEL (out), 28 DS1 (out), 29 DS0 (out), 30 WRDATA (out), 31 PS1 (out), 32 PS0 (out), 33 FLT/T0 (in), 34 WP/TS (in), 35 READY (in), 36 HDL (out), 37 FR/STP (out), 38 LCT/DR (out), 39 ~{RW}SEEK (out), 40 VCC (power) hidden to VCC
2 alternate drawings of the same symbol

## 8273
designator U?
footprint DIP-40
pins: 1 FLGDET (out), 2 TxINT (out), 3 CLK (in), 4 RESET (in), 5 TxDACK (in), 6 TxDRQ (out), 7 RxDACK (in), 8 RxDRQ (out), 9 RD (in), 10 WR (in), 11 RxINT (out), 12 DB0 (hiz), 13 DB1 (hiz), 14 DB2 (hiz), 15 DB3 (hiz), 16 DB4 (hiz), 17 DB5 (hiz), 18 DB6 (hiz), 19 DB7 (hiz), 20 GND (power) hidden to GND, 21 A0 (in), 22 A1 (in), 23 DPLL (out), 24 CS (in), 25 32*CLK (in), 26 RxD (in), 27 RxC (in), 28 TxC (in), 29 TxD (out), 30 CTS (in), 31 CD (in), 32 PA2 (in), 33 PA3 (in), 34 PA4 (in), 35 RTS (out), 36 PB1 (out), 37 PB2 (out), 38 PB3 (out), 39 PB4 (out), 40 VCC (power) hidden to VCC
2 alternate drawings of the same symbol

## 8274
designator U?
footprint DIP-40
pins: 1 CLK (in), 2 RESET (in), 3 ~{CD}A (in), 4 ~{RxC}B (in), 5 ~{CD}B (in), 6 ~{CTS}B (in), 7 ~{TxC}B (in), 8 TxDB (out), 9 RxDB (in), 10 ~{S}/~{RTS}B (io), 11 RDYBTA (out), 12 DB7 (hiz), 13 DB6 (hiz), 14 DB5 (hiz), 15 DB4 (hiz), 16 DB3 (hiz), 17 DB2 (hiz), 18 DB1 (hiz), 19 DB0 (hiz), 20 GND (power) hidden to GND, 21 WR (in), 22 RD (in), 23 CS (in), 24 A1 (in), 25 A0 (in), 26 ~{DTR}B (out), 27 INTA (in), 28 INT (out), 29 ~{IPI}RDB (io), 30 ~{IPO}TDB (out), 31 ~{DTR}A (out), 32 RDY/RA (out), 33 ~{SYNDE}A (io), 34 RxDA (in), 35 ~{RxC}A (in), 36 ~{TxC}A (in), 37 TxDA (out), 38 ~{RTS}A (out), 39 ~{CTS}A (in), 40 VCC (power) hidden to VCC
2 alternate drawings of the same symbol

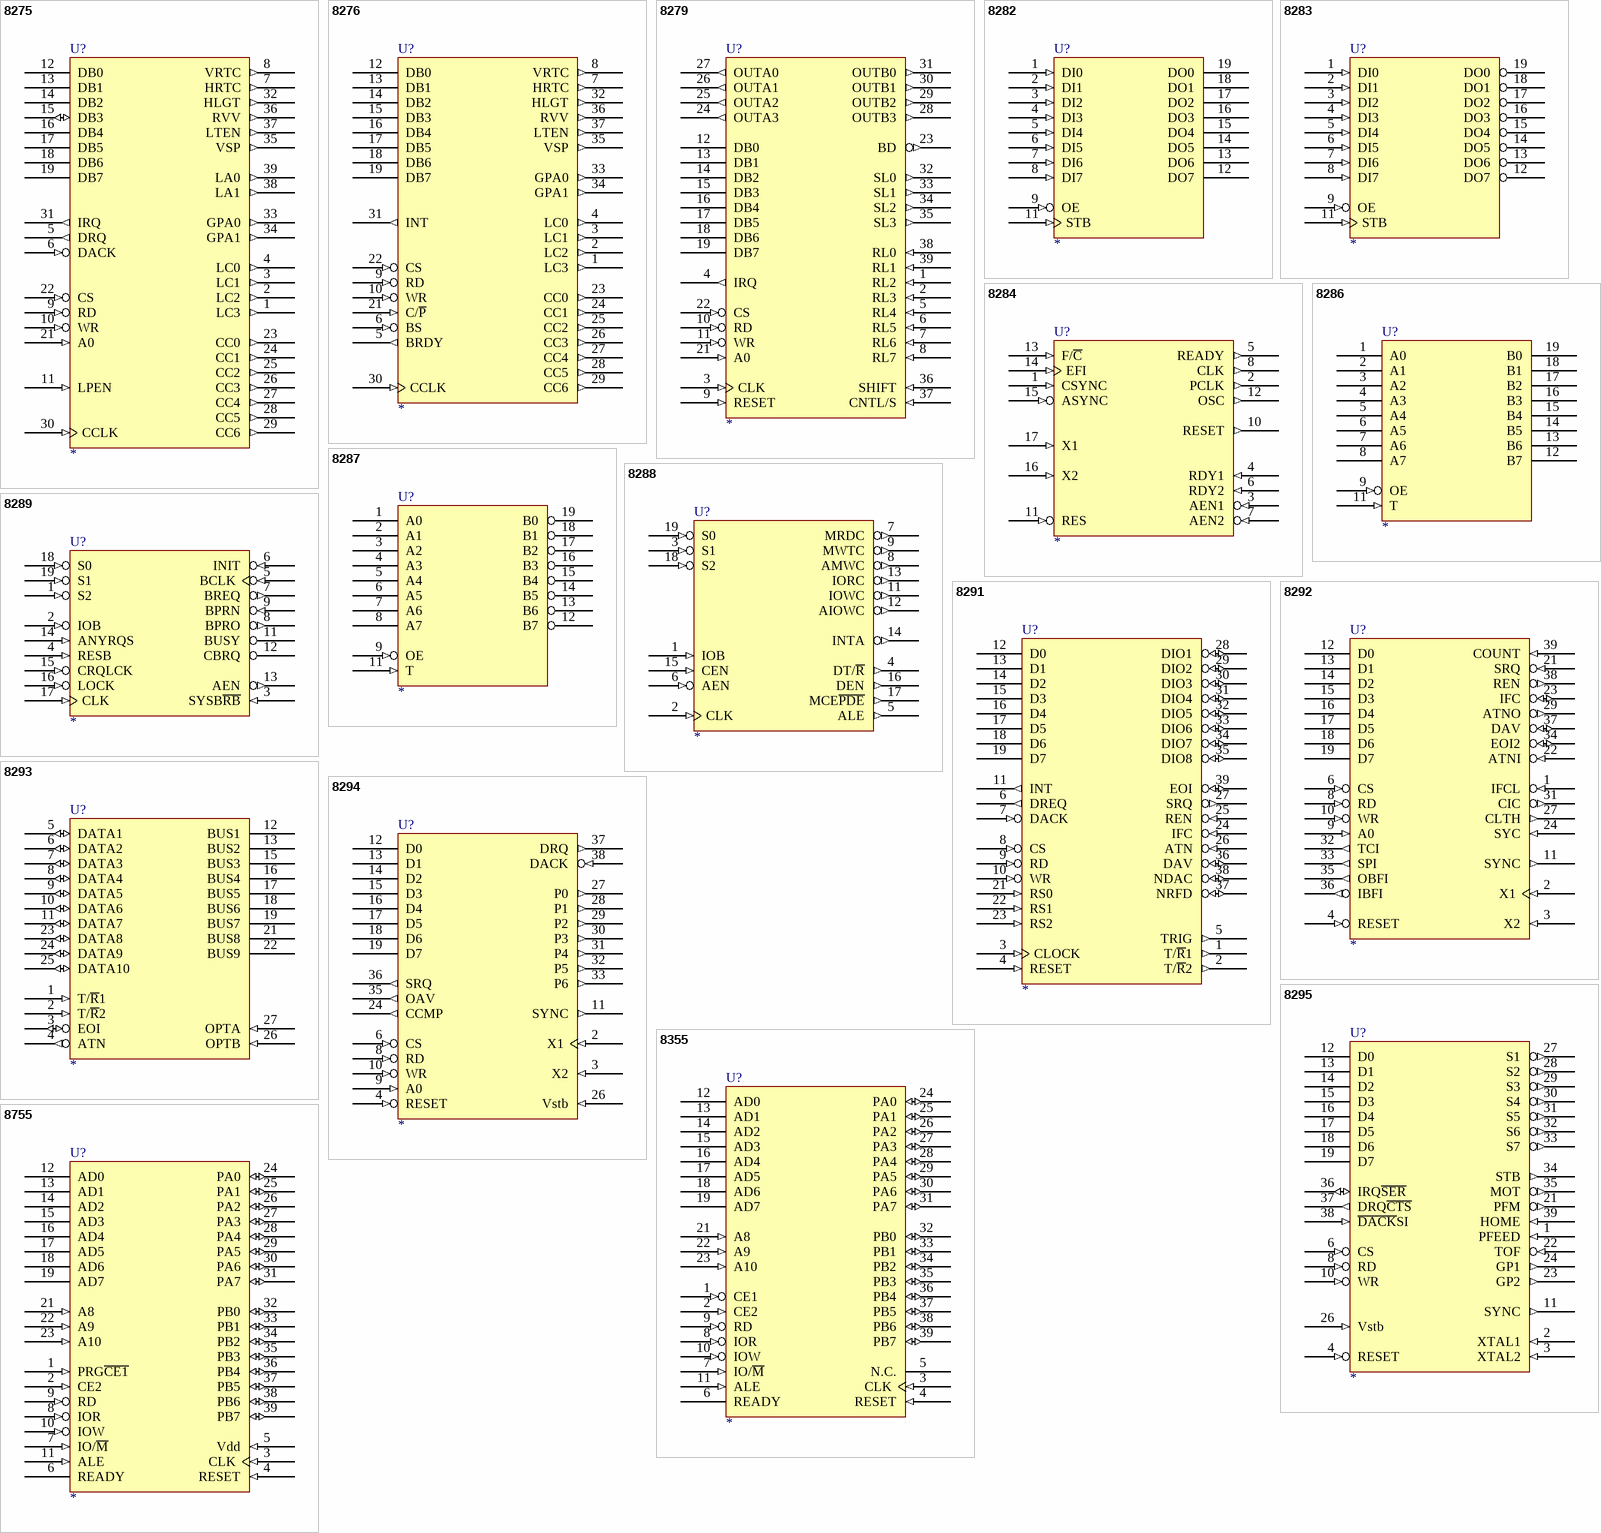
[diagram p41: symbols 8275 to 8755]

## 8275
designator U?
footprint DIP-40
pins: 1 LC3 (out), 2 LC2 (out), 3 LC1 (out), 4 LC0 (out), 5 DRQ (out), 6 DACK (in), 7 HRTC (out), 8 VRTC (out), 9 RD (in), 10 WR (in), 11 LPEN (in), 12 DB0 (hiz), 13 DB1 (hiz), 14 DB2 (hiz), 15 DB3 (io), 16 DB4 (hiz), 17 DB5 (hiz), 18 DB6 (hiz), 19 DB7 (hiz), 20 GND (power) hidden to GND, 21 A0 (in), 22 CS (in), 23 CC0 (out), 24 CC1 (out), 25 CC2 (out), 26 CC3 (out), 27 CC4 (out), 28 CC5 (out), 29 CC6 (out), 30 CCLK (in), 31 IRQ (out), 32 HLGT (out), 33 GPA0 (out), 34 GPA1 (out), 35 VSP (out), 36 RVV (out), 37 LTEN (out), 38 LA1 (out), 39 LA0 (out), 40 VCC (power) hidden to VCC
2 alternate drawings of the same symbol

## 8276
designator U?
footprint DIP-40
pins: 1 LC3 (out), 2 LC2 (out), 3 LC1 (out), 4 LC0 (out), 5 BRDY (out), 6 BS (in), 7 HRTC (out), 8 VRTC (out), 9 RD (in), 10 WR (in), 12 DB0 (hiz), 13 DB1 (hiz), 14 DB2 (hiz), 15 DB3 (hiz), 16 DB4 (hiz), 17 DB5 (hiz), 18 DB6 (hiz), 19 DB7 (hiz), 20 GND (power) hidden to GND, 21 C/~{P} (in), 22 CS (in), 23 CC0 (out), 24 CC1 (out), 25 CC2 (out), 26 CC3 (out), 27 CC4 (out), 28 CC5 (out), 29 CC6 (out), 30 CCLK (in), 31 INT (out), 32 HLGT (out), 33 GPA0 (out), 34 GPA1 (out), 35 VSP (out), 36 RVV (out), 37 LTEN (out), 40 VCC (power) hidden to VCC
2 alternate drawings of the same symbol

## 8279
designator U?
footprint DIP-40
pins: 1 RL2 (in), 2 RL3 (in), 3 CLK (in), 4 IRQ (out), 5 RL4 (in), 6 RL5 (in), 7 RL6 (in), 8 RL7 (in), 9 RESET (in), 10 RD (in), 11 WR (in), 12 DB0 (hiz), 13 DB1 (hiz), 14 DB2 (hiz), 15 DB3 (hiz), 16 DB4 (hiz), 17 DB5 (hiz), 18 DB6 (hiz), 19 DB7 (hiz), 20 GND (power) hidden to GND, 21 A0 (in), 22 CS (in), 23 BD (out), 24 OUTA3 (out), 25 OUTA2 (out), 26 OUTA1 (out), 27 OUTA0 (out), 28 OUTB3 (out), 29 OUTB2 (out), 30 OUTB1 (out), 31 OUTB0 (out), 32 SL0 (out), 33 SL1 (out), 34 SL2 (out), 35 SL3 (out), 36 SHIFT (in), 37 CNTL/S (in), 38 RL0 (in), 39 RL1 (in), 40 VCC (power) hidden to VCC
2 alternate drawings of the same symbol

## 8282
designator U?
footprint DIP-20
pins: 1 DI0 (in), 2 DI1 (in), 3 DI2 (in), 4 DI3 (in), 5 DI4 (in), 6 DI5 (in), 7 DI6 (in), 8 DI7 (in), 9 OE (in), 10 GND (power) hidden to GND, 11 STB (in), 12 DO7 (hiz), 13 DO6 (hiz), 14 DO5 (hiz), 15 DO4 (hiz), 16 DO3 (hiz), 17 DO2 (hiz), 18 DO1 (hiz), 19 DO0 (hiz), 20 VCC (power) hidden to VCC
2 alternate drawings of the same symbol

## 8283
designator U?
footprint DIP-20
pins: 1 DI0 (in), 2 DI1 (in), 3 DI2 (in), 4 DI3 (in), 5 DI4 (in), 6 DI5 (in), 7 DI6 (in), 8 DI7 (in), 9 OE (in), 10 GND (power) hidden to GND, 11 STB (in), 12 DO7 (hiz), 13 DO6 (hiz), 14 DO5 (hiz), 15 DO4 (hiz), 16 DO3 (hiz), 17 DO2 (hiz), 18 DO1 (hiz), 19 DO0 (hiz), 20 VCC (power) hidden to VCC
2 alternate drawings of the same symbol

## 8284
designator U?
footprint DIP-18
pins: 1 CSYNC (in), 2 PCLK (out), 3 AEN1 (in), 4 RDY1 (in), 5 READY (out), 6 RDY2 (in), 7 AEN2 (in), 8 CLK (out), 9 GND (power) hidden to GND, 10 RESET (out), 11 RES (in), 12 OSC (out), 13 F/~{C} (in), 14 EFI (in), 15 ASYNC (in), 16 X2 (in), 17 X1 (in), 18 VCC (power) hidden to VCC
2 alternate drawings of the same symbol

## 8286
designator U?
footprint DIP-20
pins: 1 A0 (hiz), 2 A1 (hiz), 3 A2 (hiz), 4 A3 (hiz), 5 A4 (hiz), 6 A5 (hiz), 7 A6 (hiz), 8 A7 (hiz), 9 OE (in), 10 GND (power) hidden to GND, 11 T (in), 12 B7 (hiz), 13 B6 (hiz), 14 B5 (hiz), 15 B4 (hiz), 16 B3 (hiz), 17 B2 (hiz), 18 B1 (hiz), 19 B0 (hiz), 20 VCC (power) hidden to VCC
2 alternate drawings of the same symbol

## 8287
designator U?
footprint DIP-20
pins: 1 A0 (hiz), 2 A1 (hiz), 3 A2 (hiz), 4 A3 (hiz), 5 A4 (hiz), 6 A5 (hiz), 7 A6 (hiz), 8 A7 (hiz), 9 OE (in), 10 GND (power) hidden to GND, 11 T (in), 12 B7 (hiz), 13 B6 (hiz), 14 B5 (hiz), 15 B4 (hiz), 16 B3 (hiz), 17 B2 (hiz), 18 B1 (hiz), 19 B0 (hiz), 20 VCC (power) hidden to VCC
2 alternate drawings of the same symbol

## 8288
designator U?
footprint DIP-20
pins: 1 IOB (in), 2 CLK (in), 3 S1 (in), 4 DT/~{R} (out), 5 ALE (out), 6 AEN (in), 7 MRDC (out), 8 AMWC (out), 9 MWTC (out), 10 GND (power) hidden to GND, 11 IOWC (out), 12 AIOWC (out), 13 IORC (out), 14 INTA (out), 15 CEN (in), 16 DEN (out), 17 MCE~{PDE} (out), 18 S2 (in), 19 S0 (in), 20 VCC (power) hidden to VCC
2 alternate drawings of the same symbol

## 8289
designator U?
footprint DIP-20
pins: 1 S2 (in), 2 IOB (in), 3 SYSB~{RB} (in), 4 RESB (in), 5 BCLK (in), 6 INIT (in), 7 BREQ (out), 8 BPRO (out), 9 BPRN (in), 10 GND (power) hidden to GND, 11 BUSY (oc), 12 CBRQ (oc), 13 AEN (out), 14 ANYRQS (in), 15 CRQLCK (in), 16 LOCK (in), 17 CLK (in), 18 S0 (in), 19 S1 (in), 20 VCC (power) hidden to VCC
2 alternate drawings of the same symbol

## 8291
designator U?
footprint DIP-40
pins: 1 T/~{R}1 (out), 2 T/~{R}2 (out), 3 CLOCK (in), 4 RESET (in), 5 TRIG (out), 6 DREQ (out), 7 DACK (in), 8 CS (in), 9 RD (in), 10 WR (in), 11 INT (out), 12 D0 (hiz), 13 D1 (hiz), 14 D2 (hiz), 15 D3 (hiz), 16 D4 (hiz), 17 D5 (hiz), 18 D6 (hiz), 19 D7 (hiz), 20 GND (power) hidden to GND, 21 RS0 (in), 22 RS1 (in), 23 RS2 (in), 24 IFC (in), 25 REN (in), 26 ATN (in), 27 SRQ (out), 28 DIO1 (io), 29 DIO2 (io), 30 DIO3 (io), 31 DIO4 (io), 32 DIO5 (io), 33 DIO6 (io), 34 DIO7 (io), 35 DIO8 (io), 36 DAV (io), 37 NRFD (io), 38 NDAC (io), 39 EOI (io), 40 VCC (power) hidden to VCC
2 alternate drawings of the same symbol

## 8292
designator U?
footprint DIP-40
pins: 1 IFCL (in), 2 X1 (in), 3 X2 (in), 4 RESET (in), 5 VCC (power) hidden to VCC, 6 CS (in), 7 GND (power) hidden to GND, 8 RD (in), 9 A0 (in), 10 WR (in), 11 SYNC (out), 12 D0 (hiz), 13 D1 (hiz), 14 D2 (hiz), 15 D3 (hiz), 16 D4 (hiz), 17 D5 (hiz), 18 D6 (hiz), 19 D7 (hiz), 20 GND (power) hidden to GND, 21 SRQ (in), 22 ATNI (in), 23 IFC (io), 24 SYC (in), 26 VCC (power) hidden to VCC, 27 CLTH (out), 29 ATNO (out), 31 CIC (out), 32 TCI (out), 33 SPI (out), 34 EOI2 (io), 35 OBFI (out), 36 IBFI (out), 37 DAV (io), 38 REN (out), 39 COUNT (in), 40 VCC (power) hidden to VCC
2 alternate drawings of the same symbol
